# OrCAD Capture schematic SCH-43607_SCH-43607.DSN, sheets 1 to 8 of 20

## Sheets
1 P01_TITLE: title: FRWYLS1046A-PA; rev: B; company: NXP Semiconductors; note: SCH-43607 PDF: SPF-43607; note: 6501 William Cannon Drive West; note: Austin, TX 78735-8598
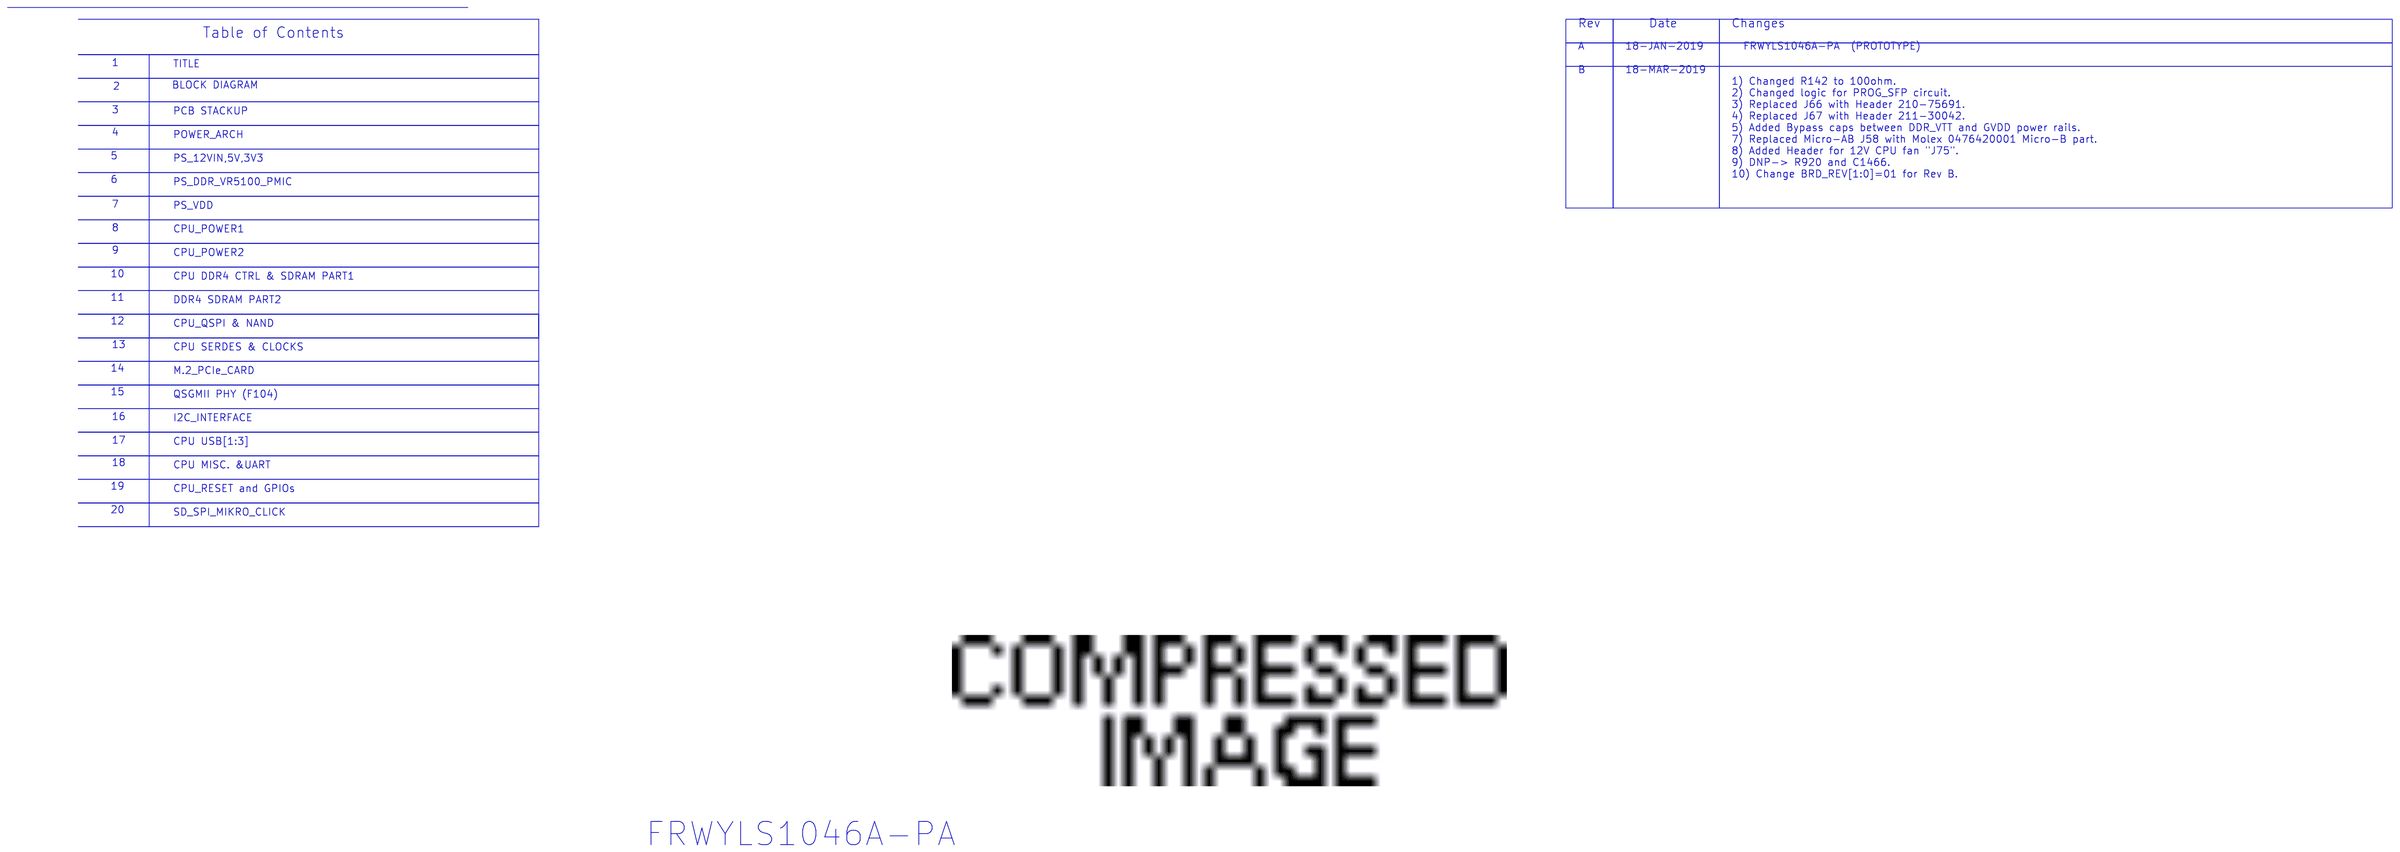
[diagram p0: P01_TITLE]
2 P02_BLOCK DIAGRAM
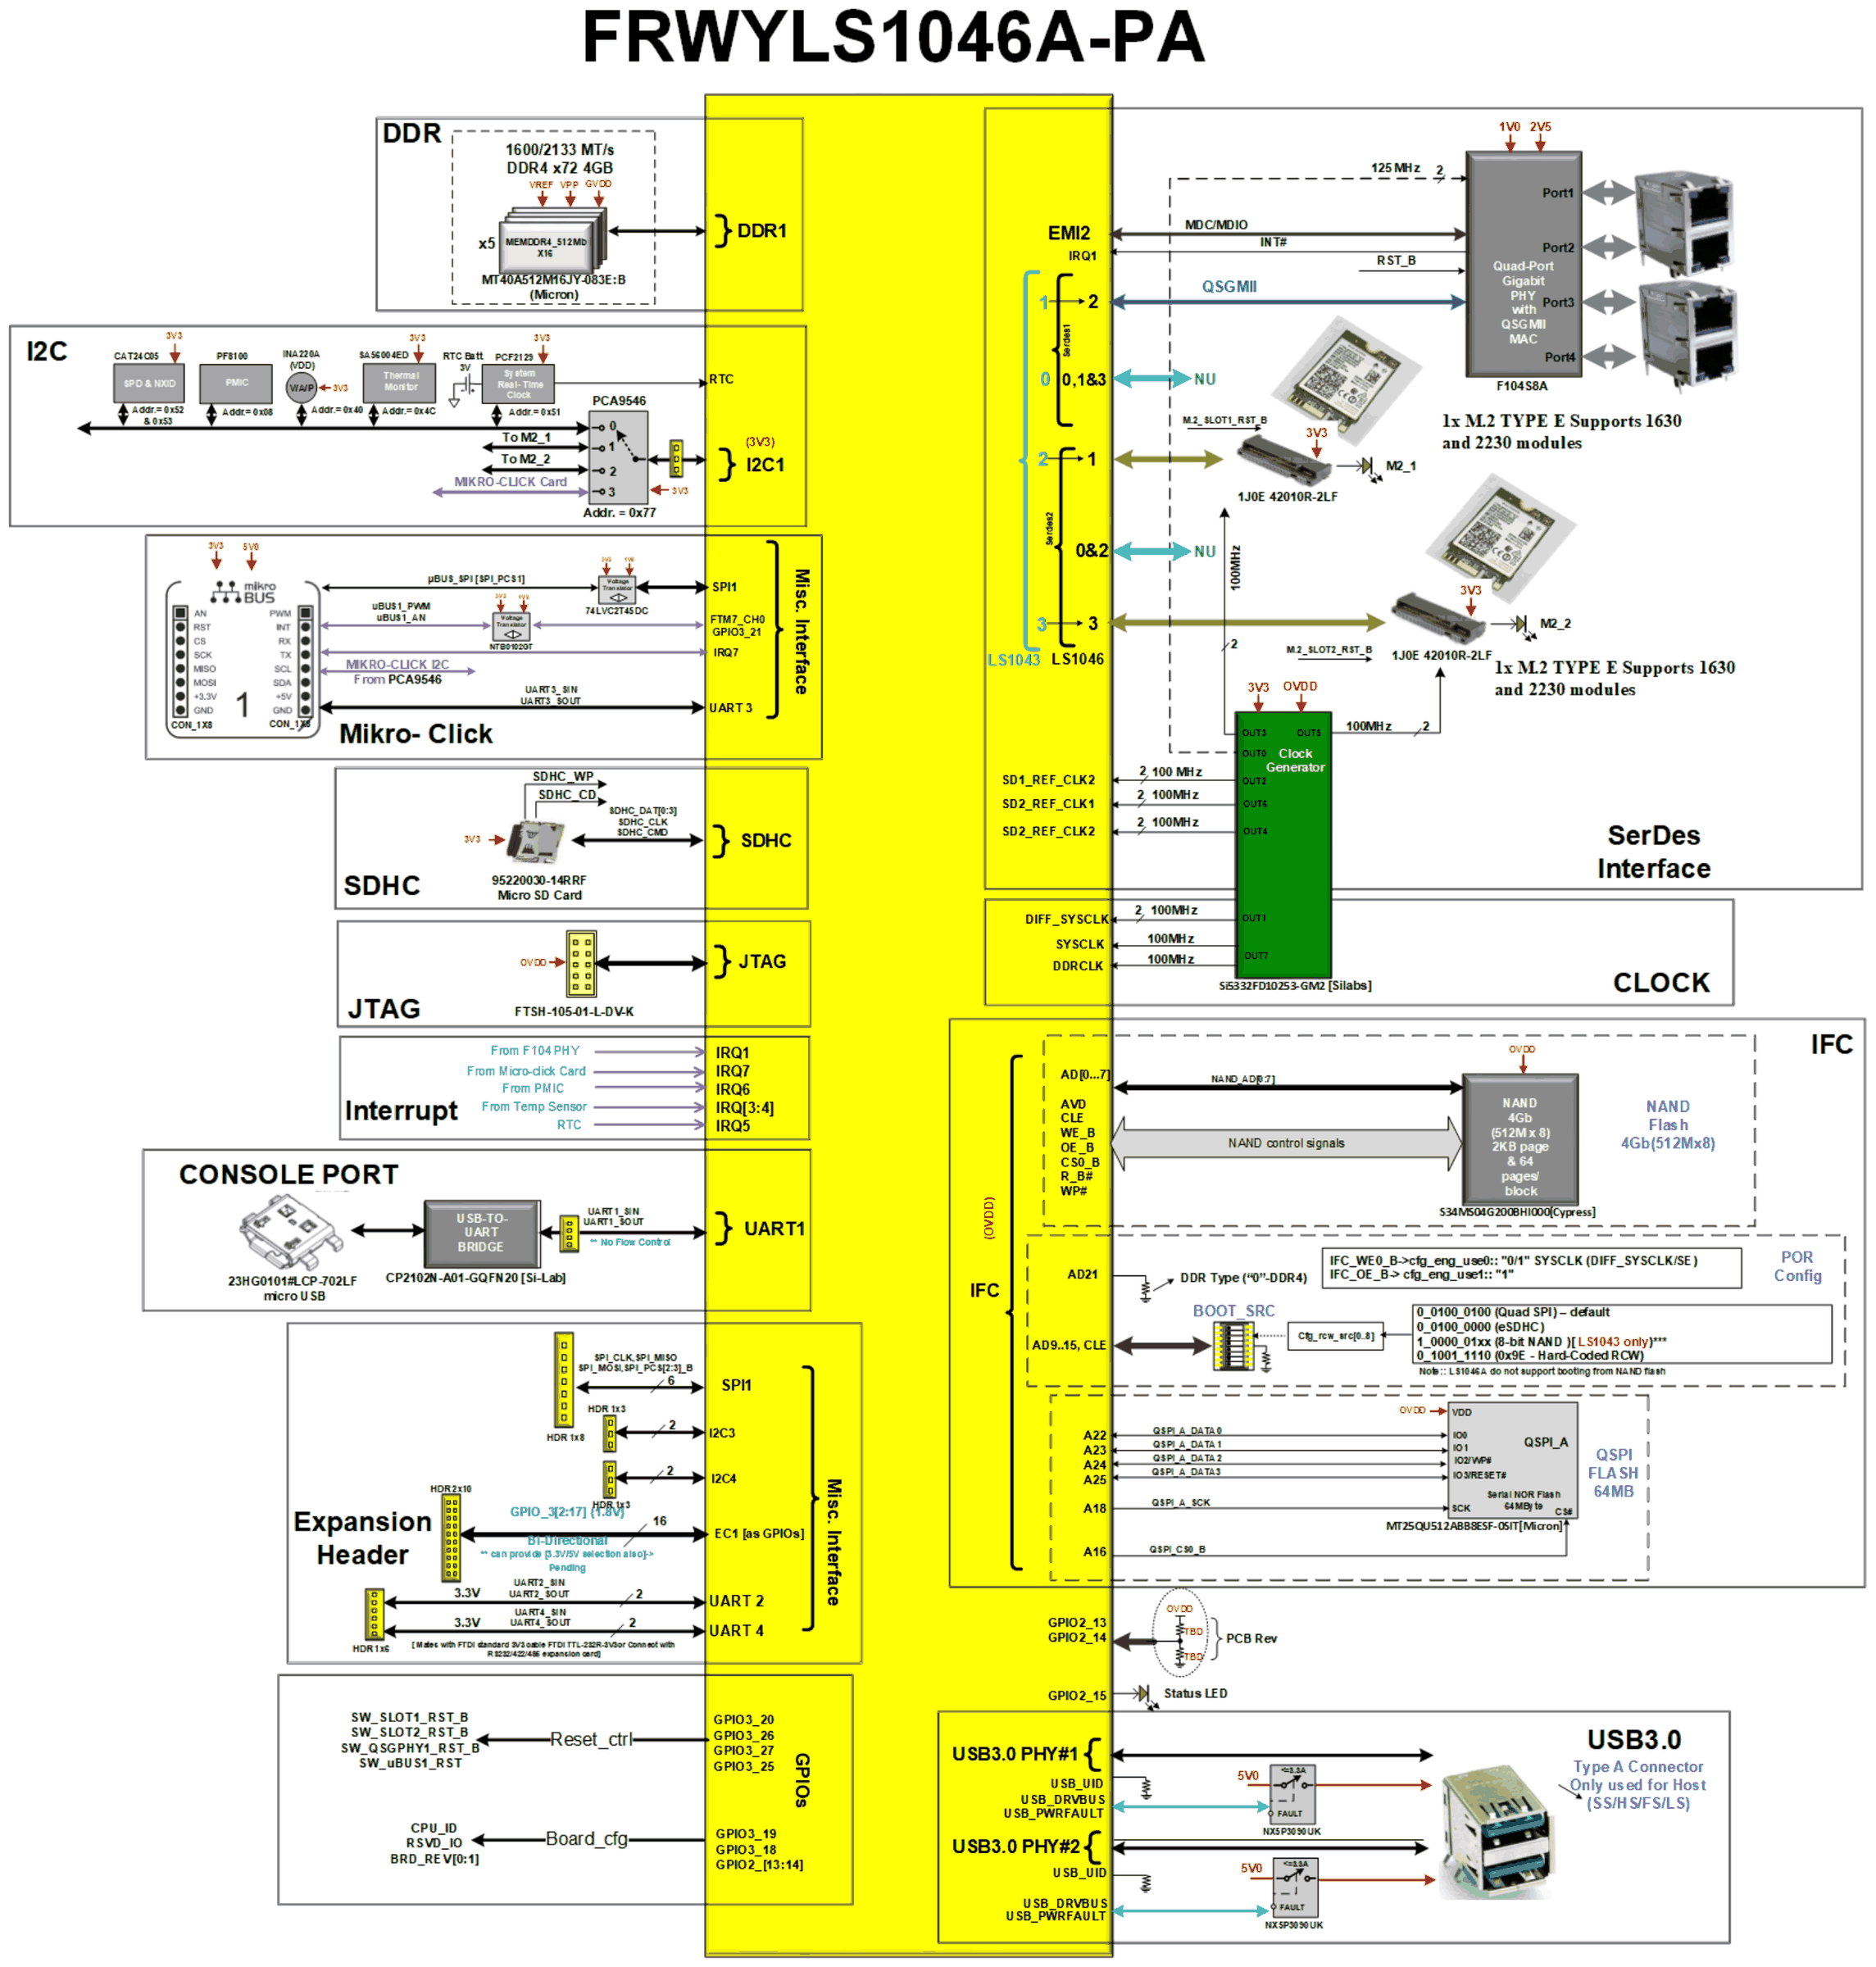
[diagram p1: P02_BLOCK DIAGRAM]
3 P03_PCB STACKUP
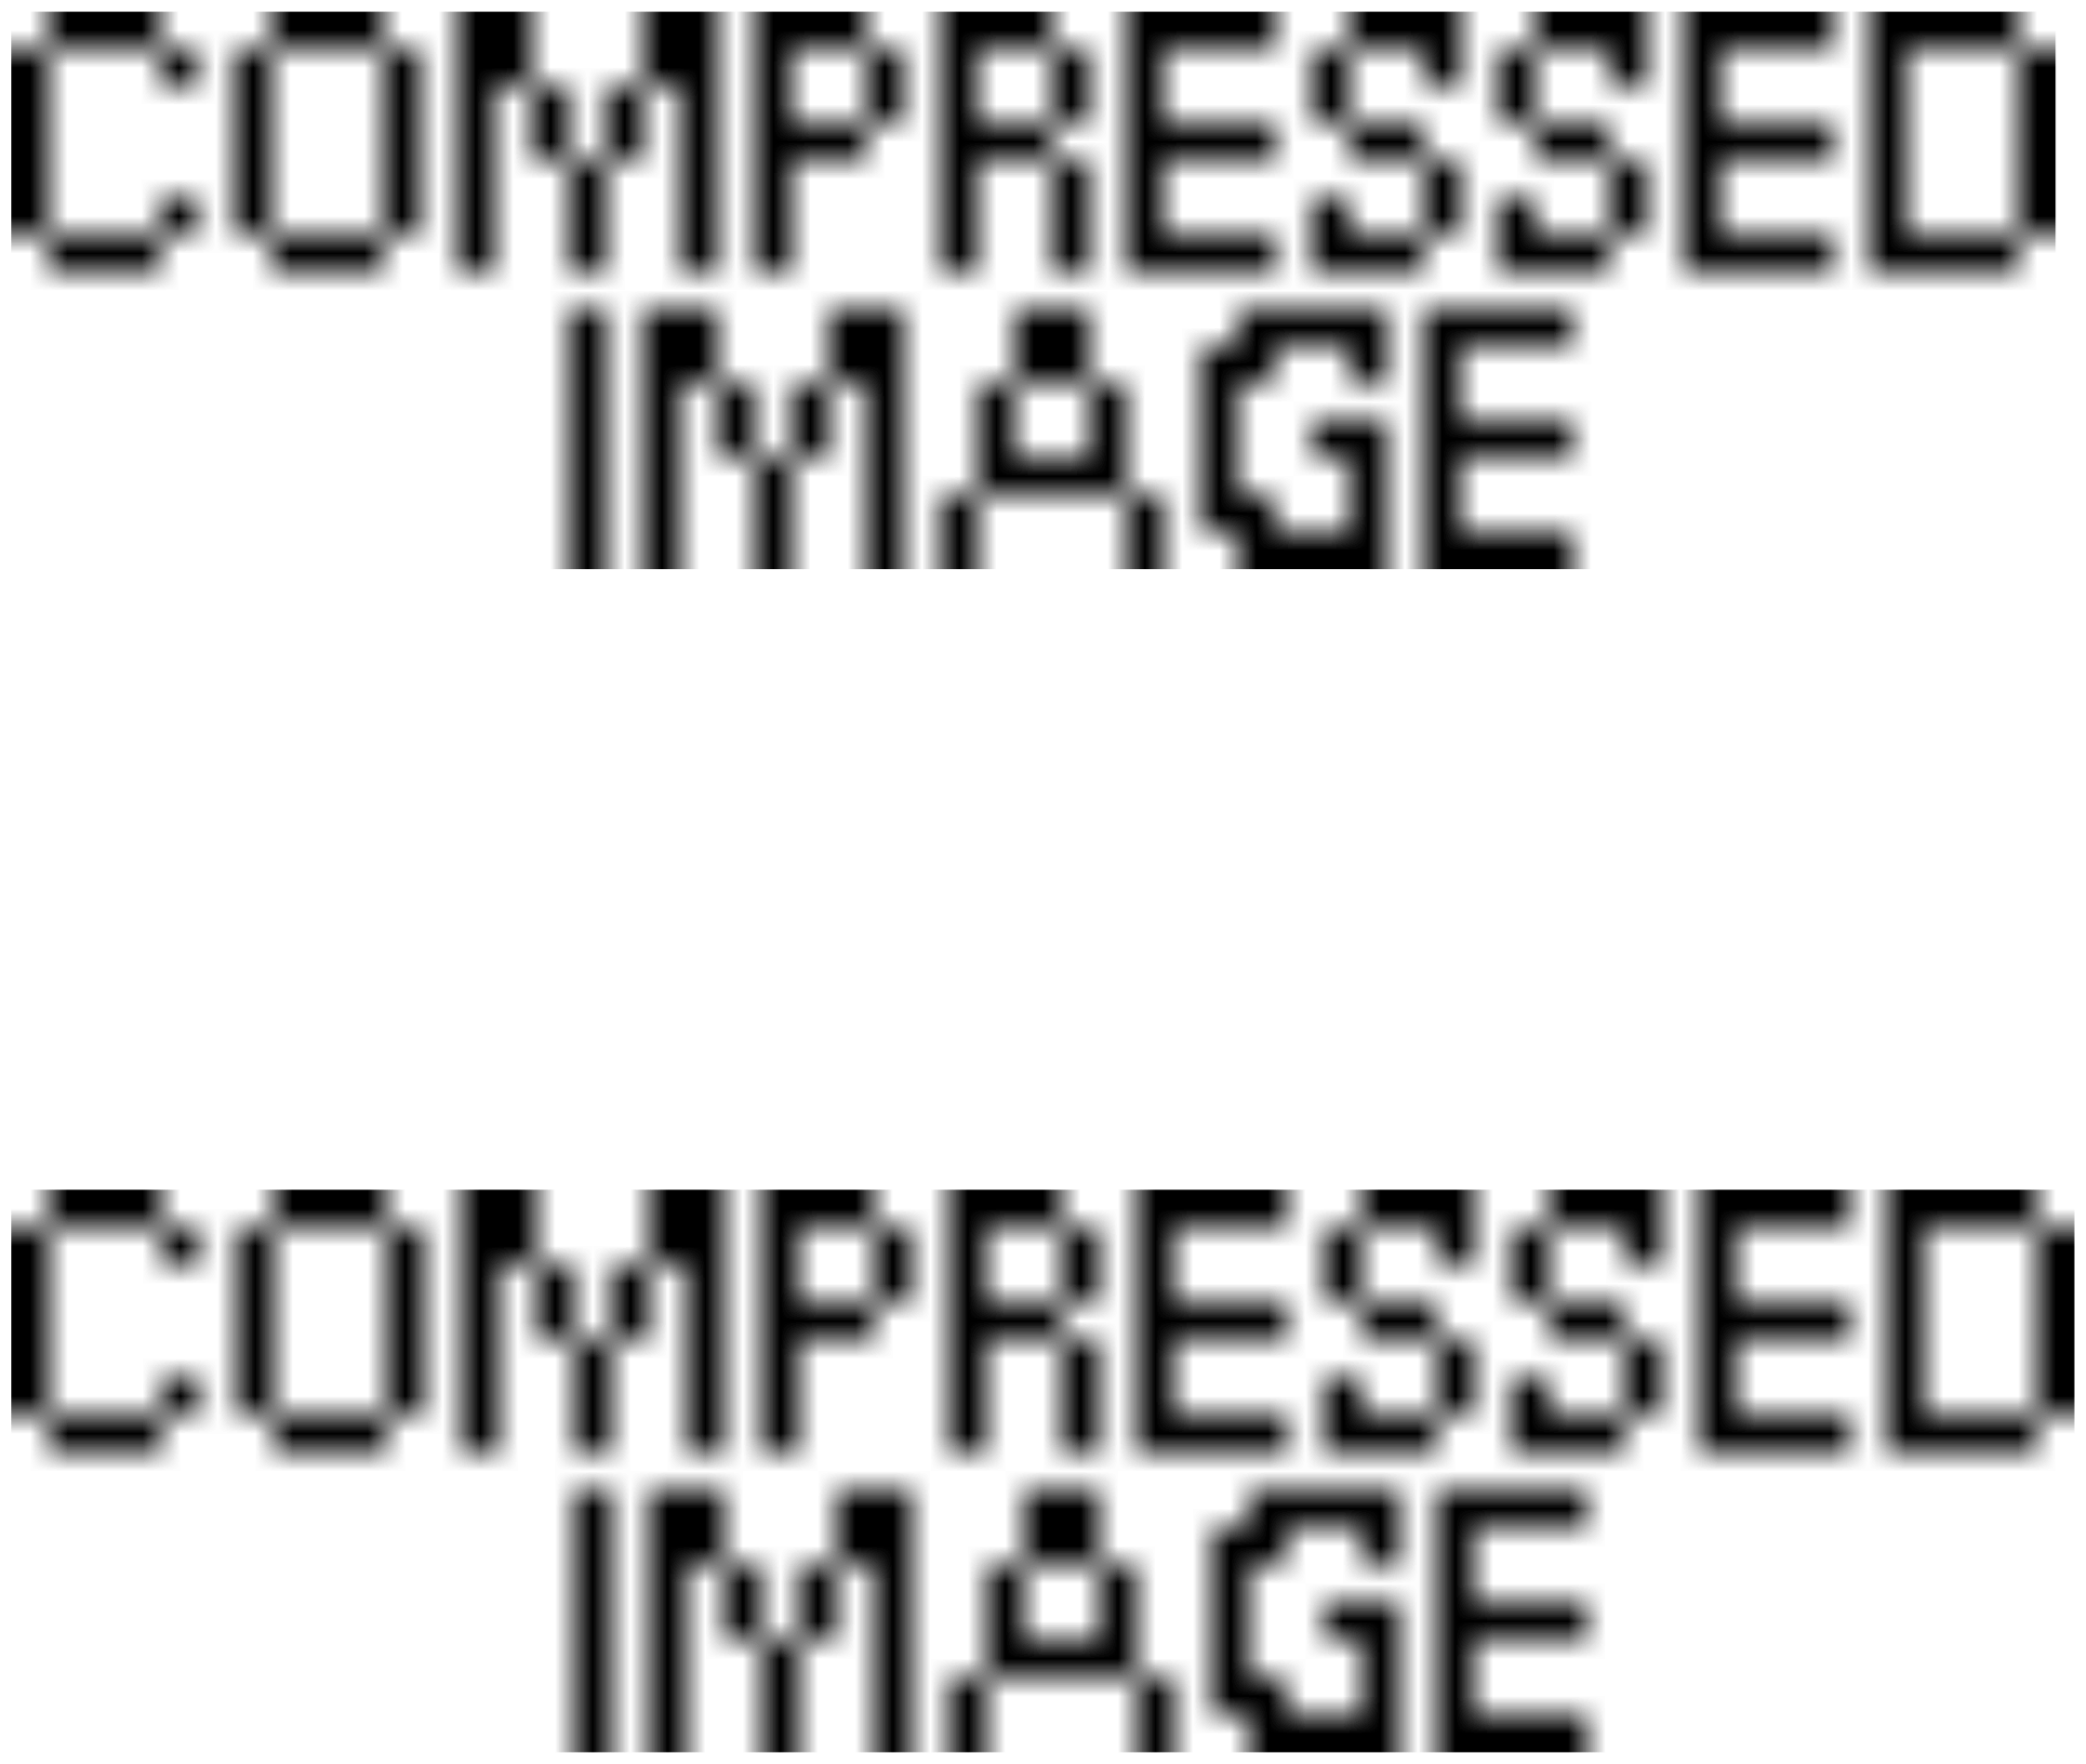
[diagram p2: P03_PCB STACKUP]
4 P04_POWER_ARCH
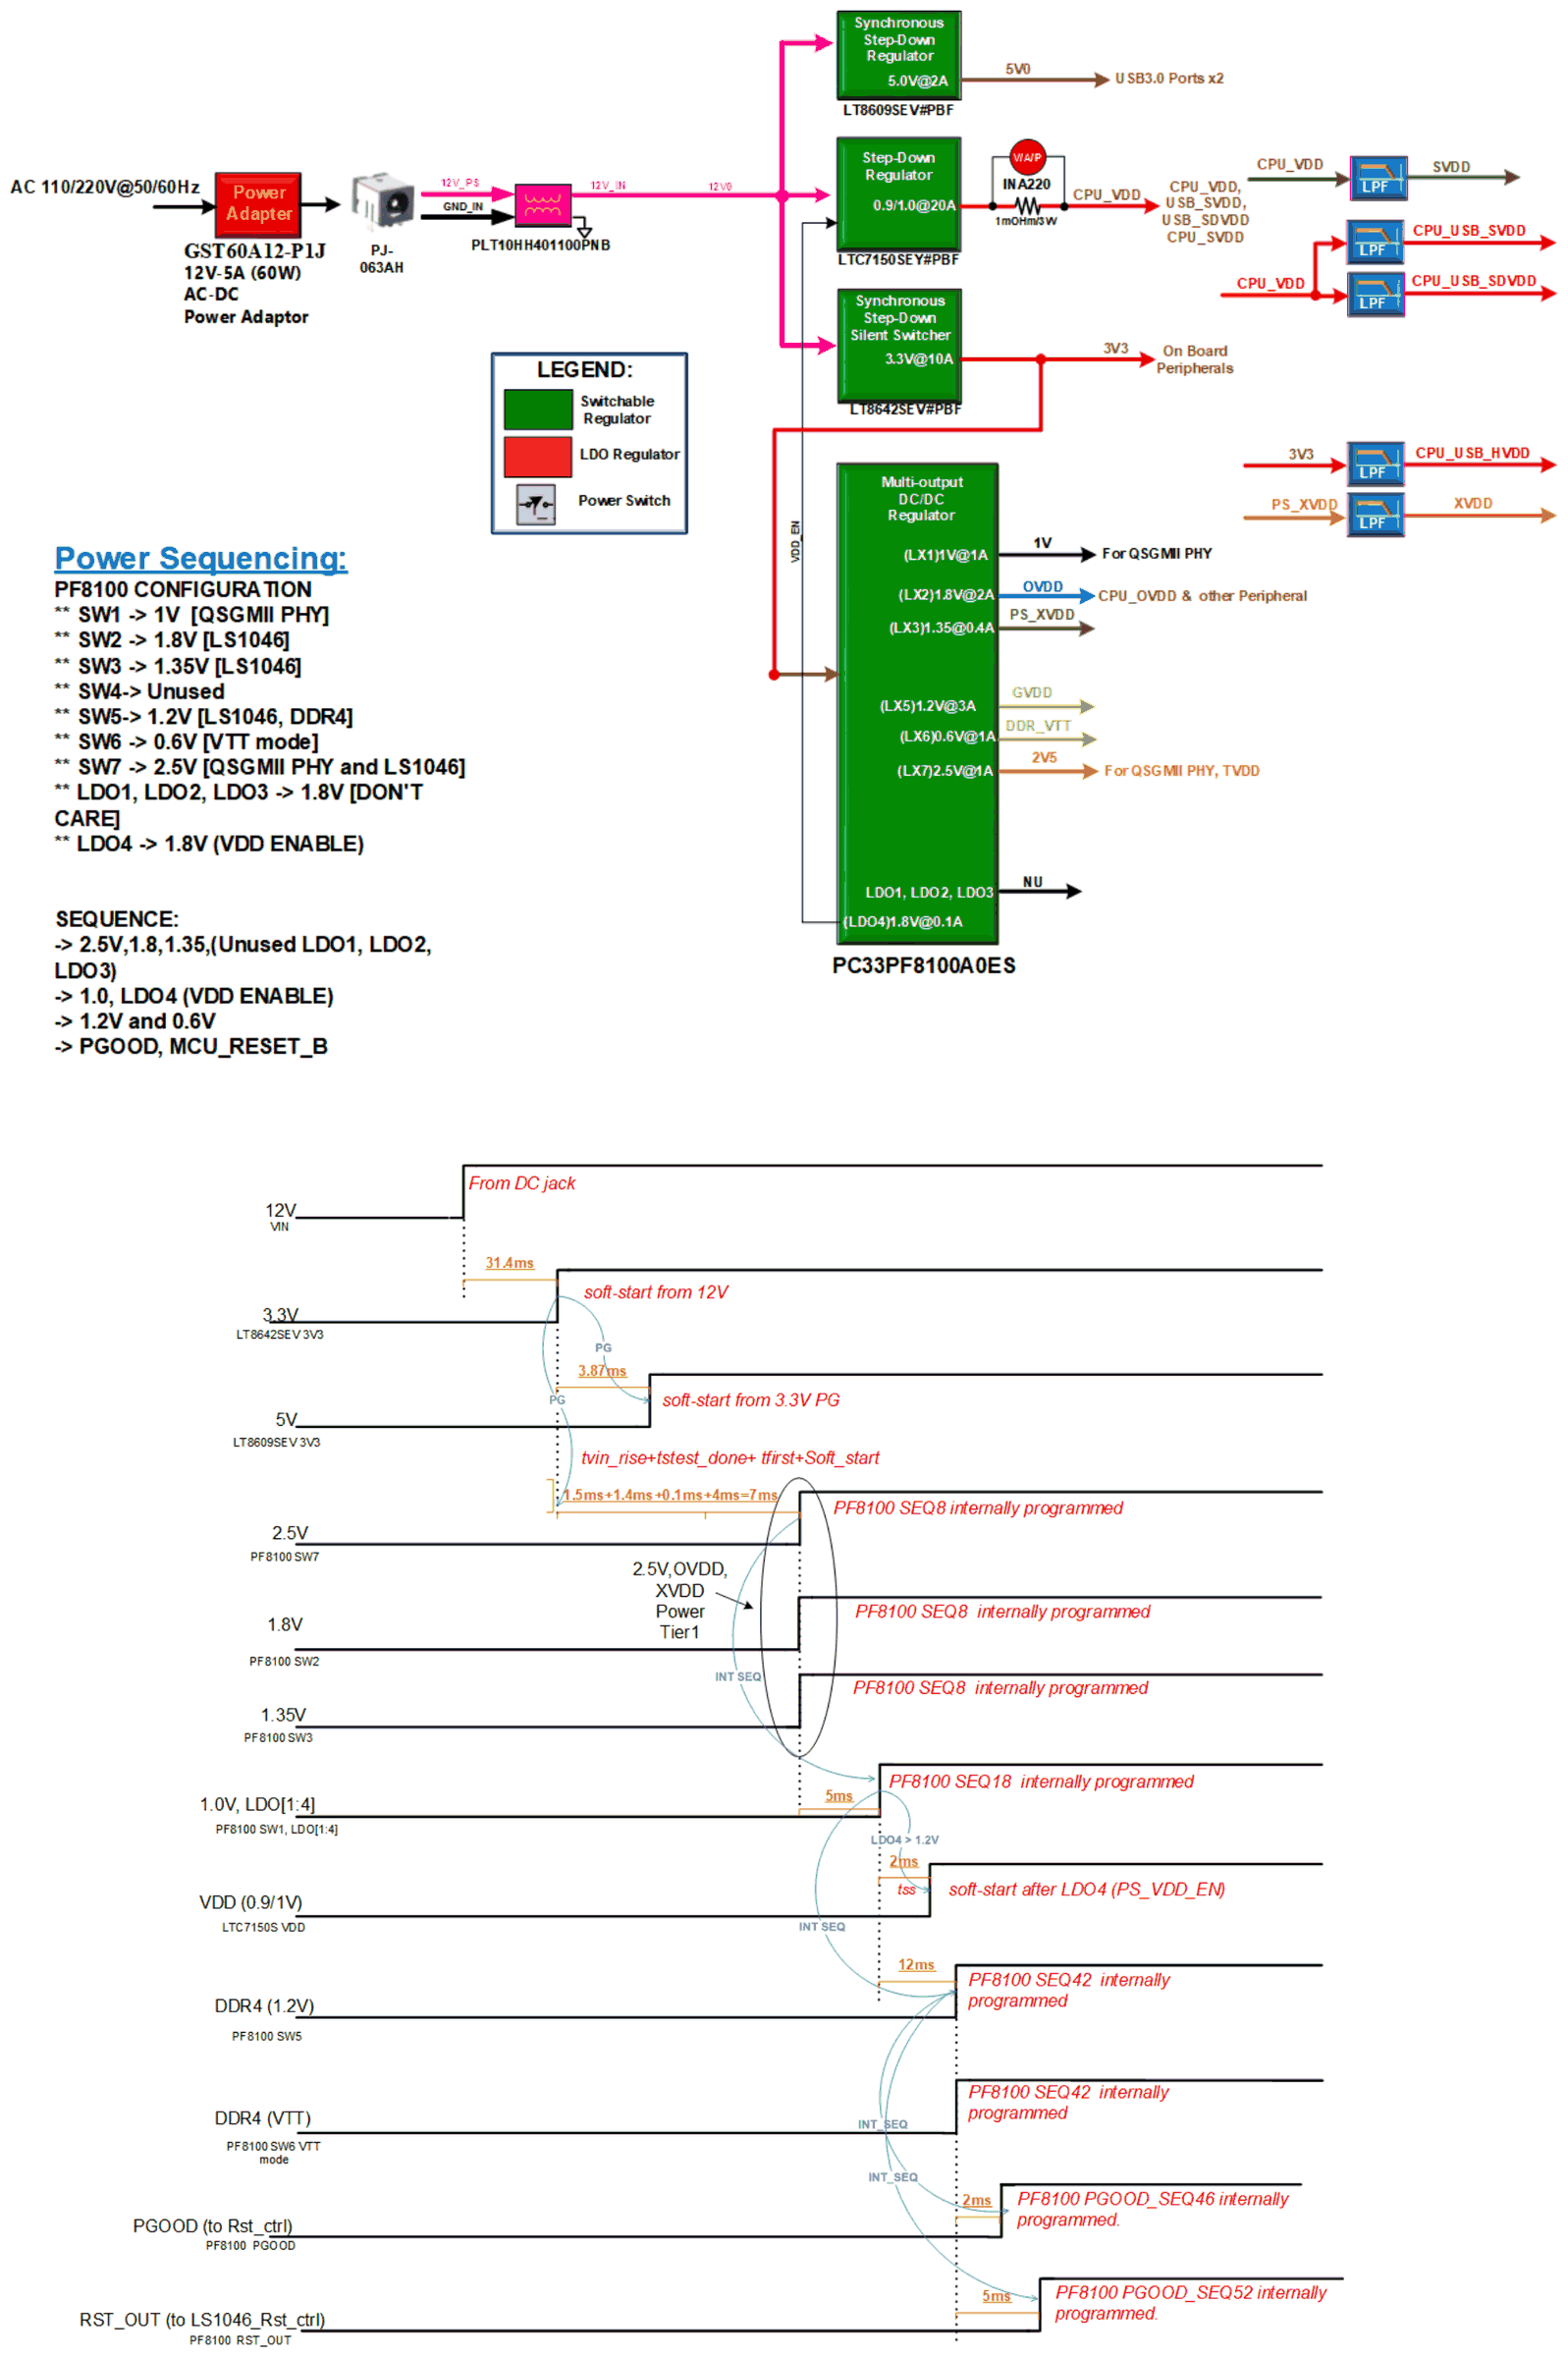
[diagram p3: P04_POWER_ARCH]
5 P05_PS_12VIN,5V,3V3: size C
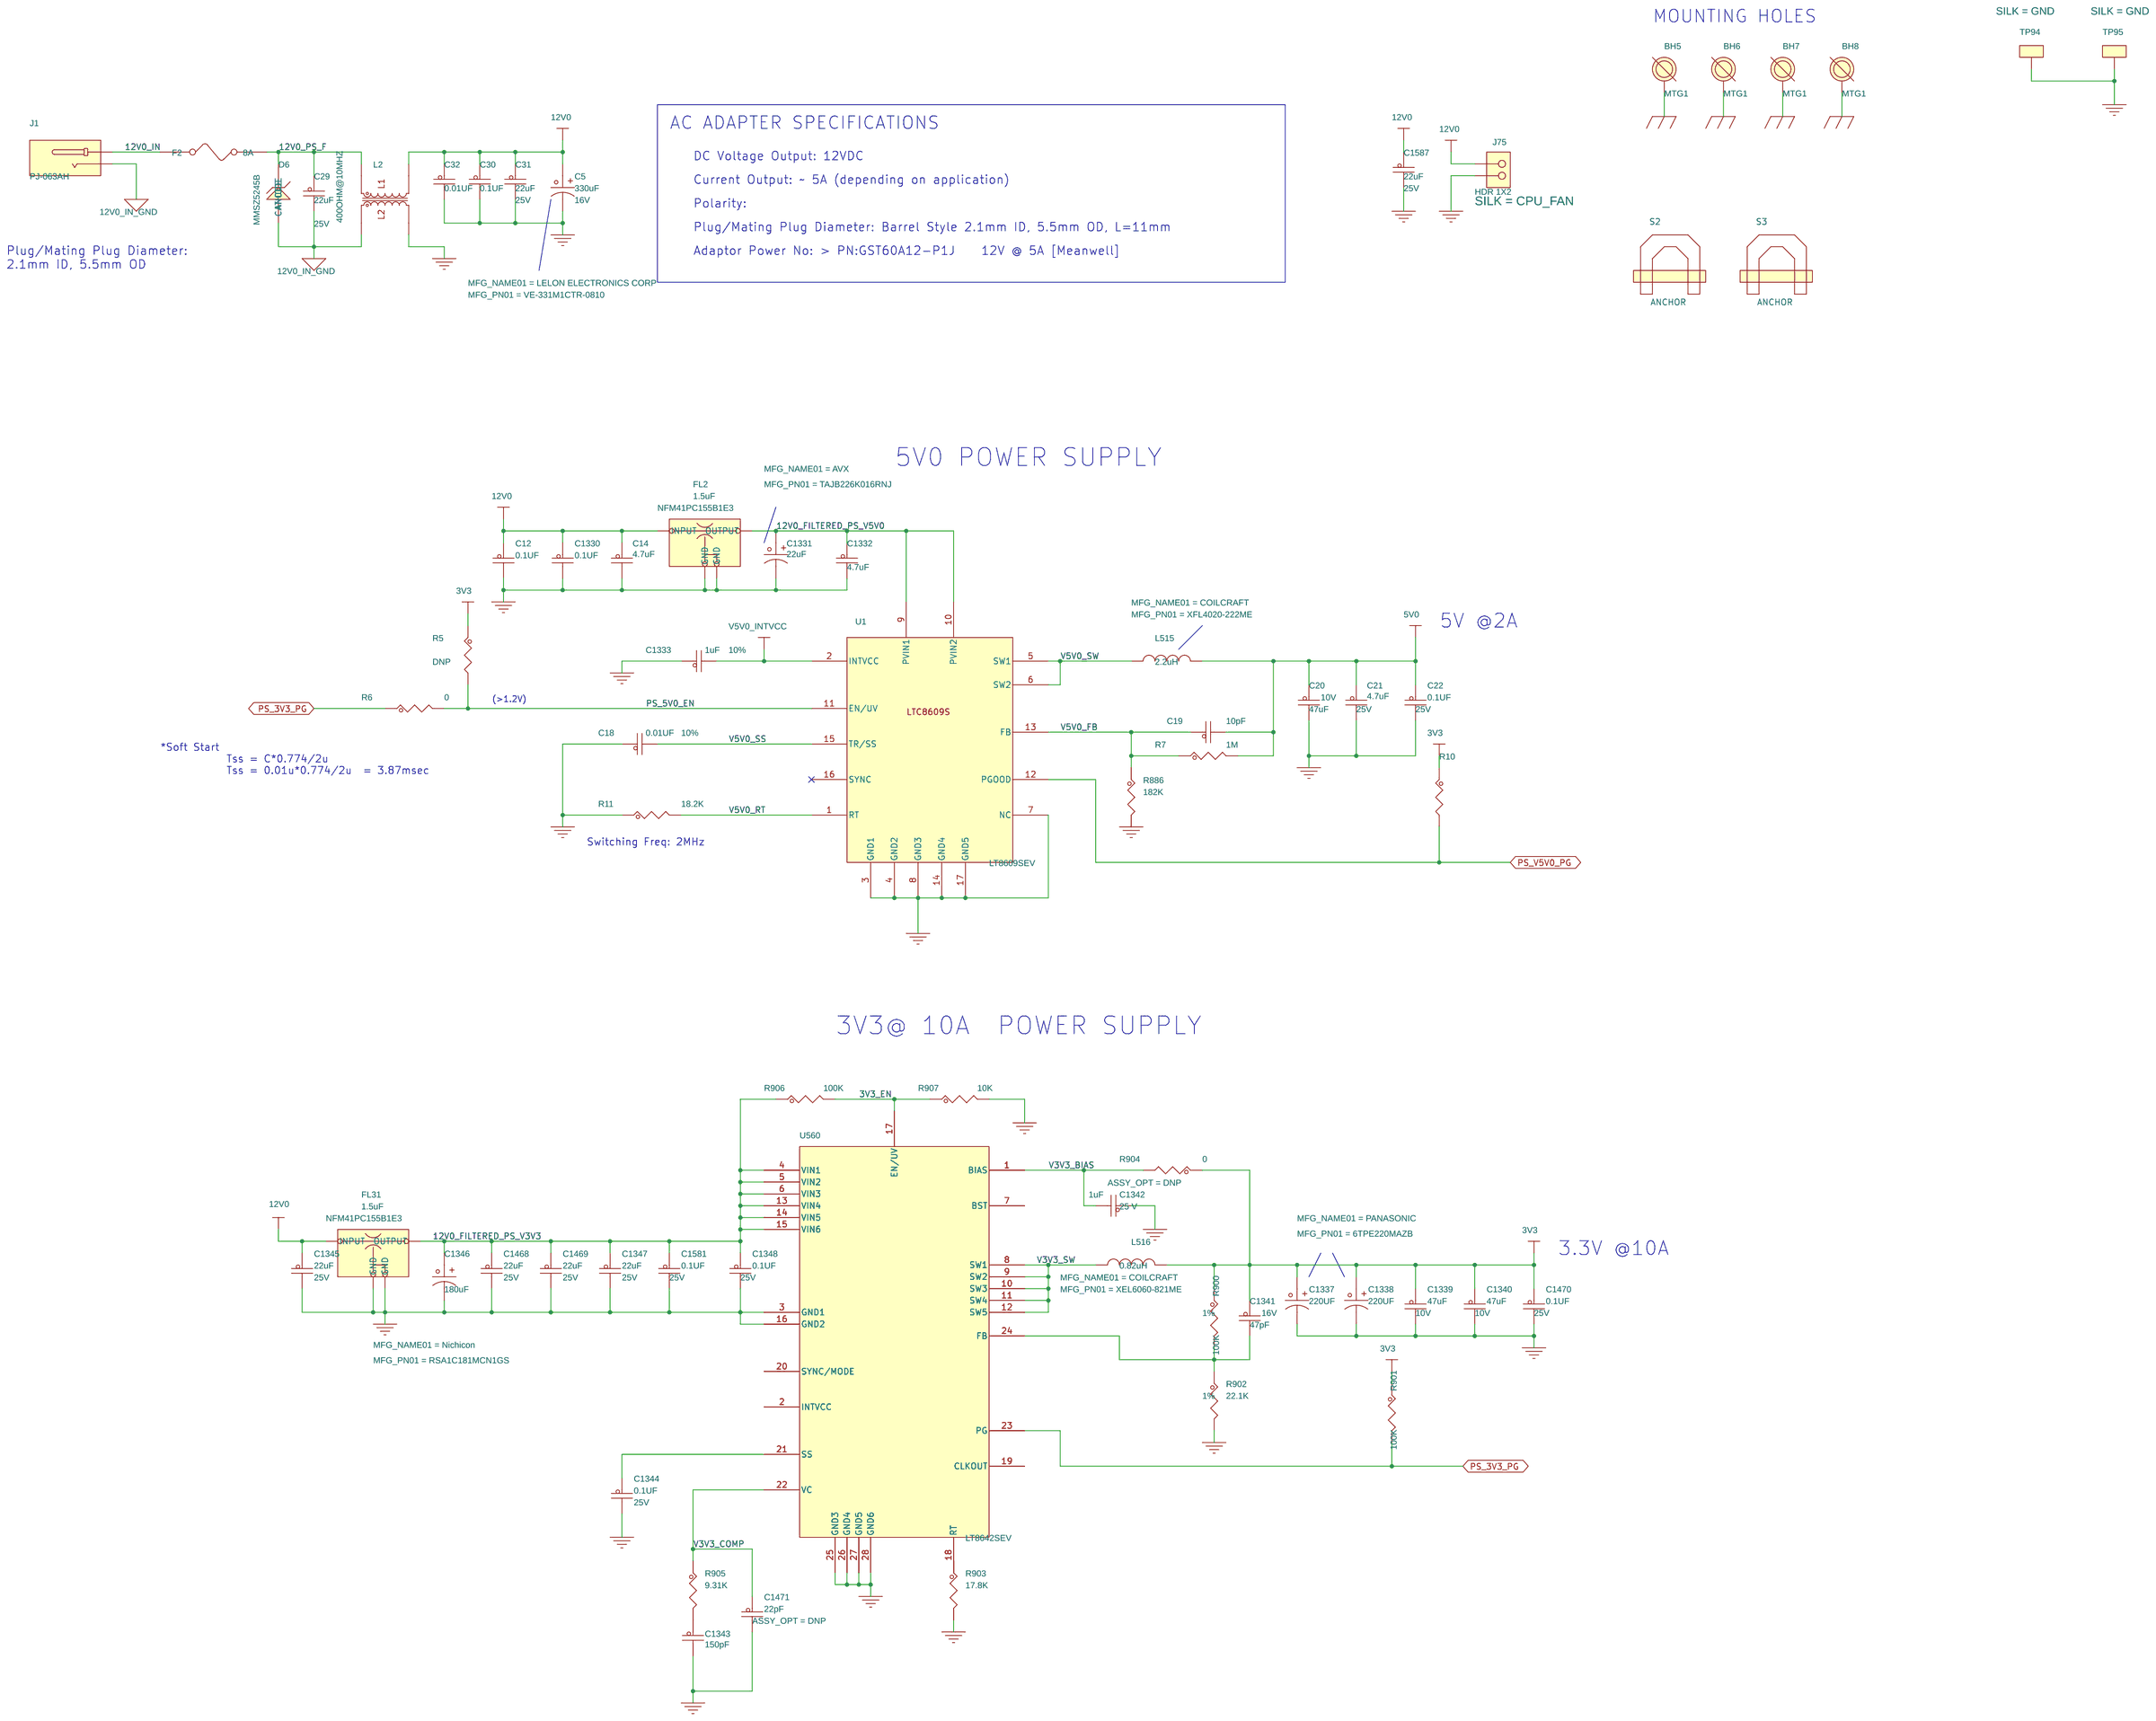
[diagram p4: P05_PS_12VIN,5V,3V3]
6 P06_PS_DDR_PF8100_PMIC: size C
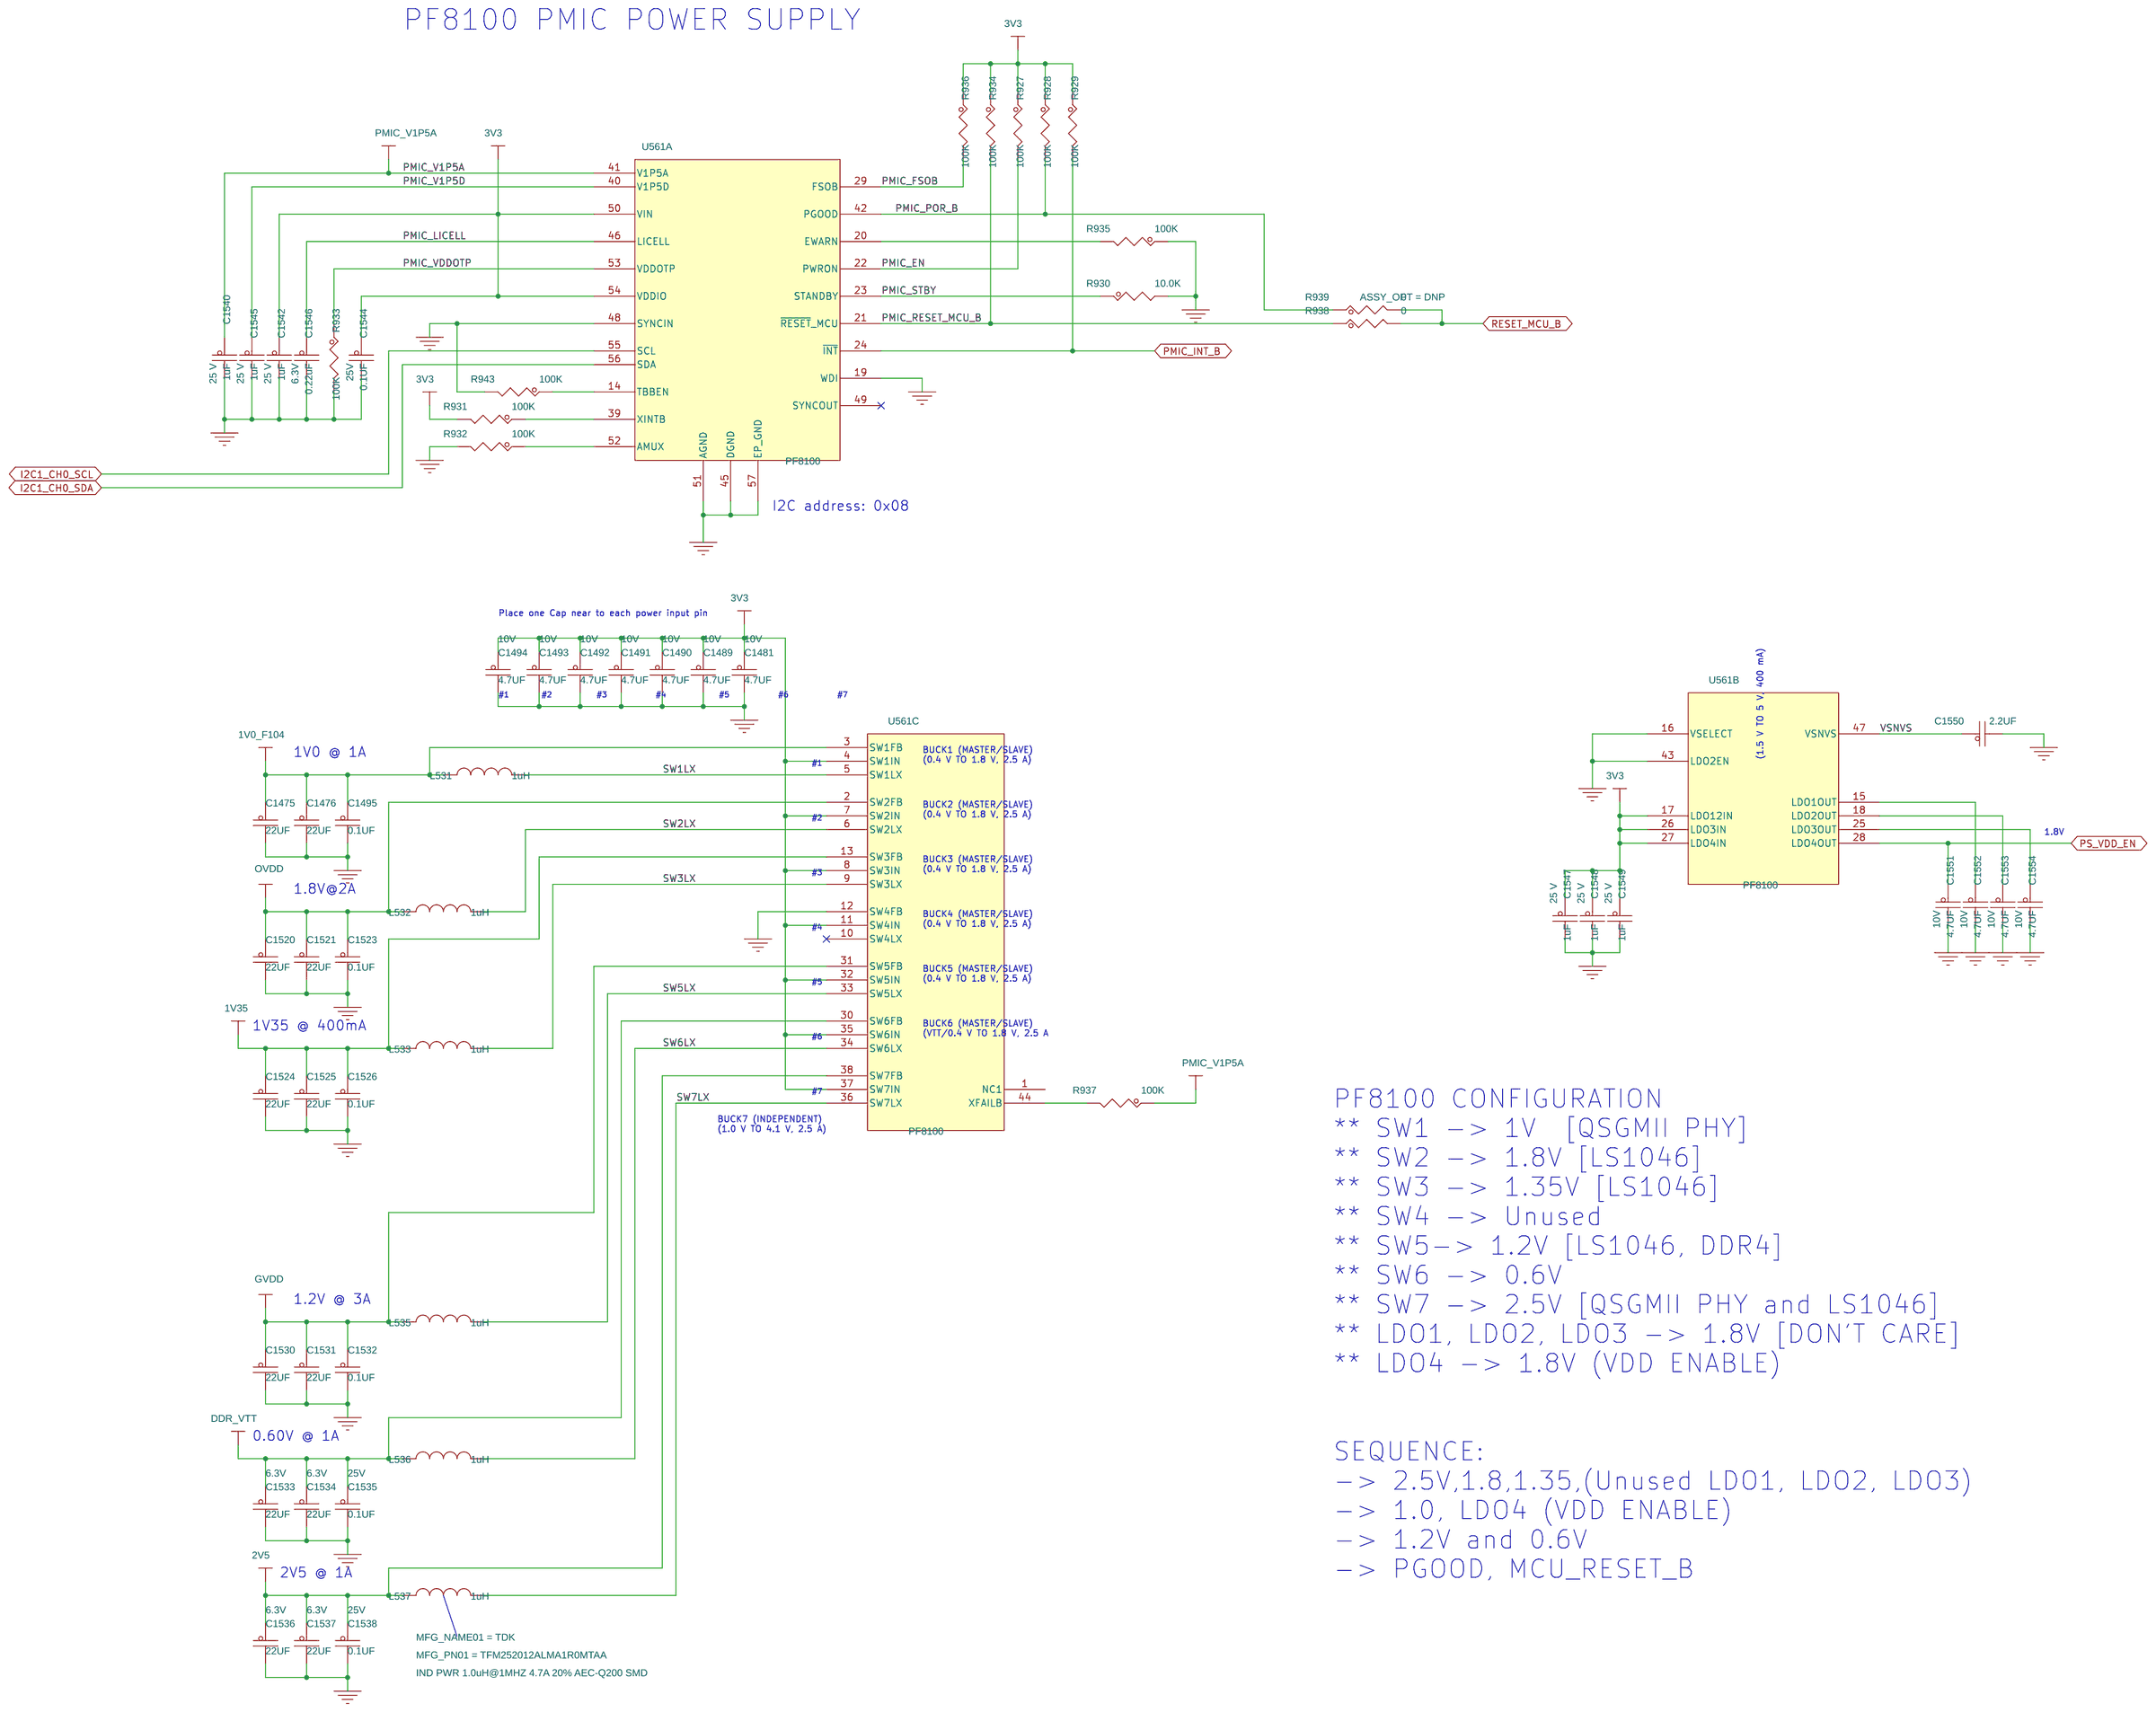
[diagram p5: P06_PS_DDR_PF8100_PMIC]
7 P07_PS_VDD: size C
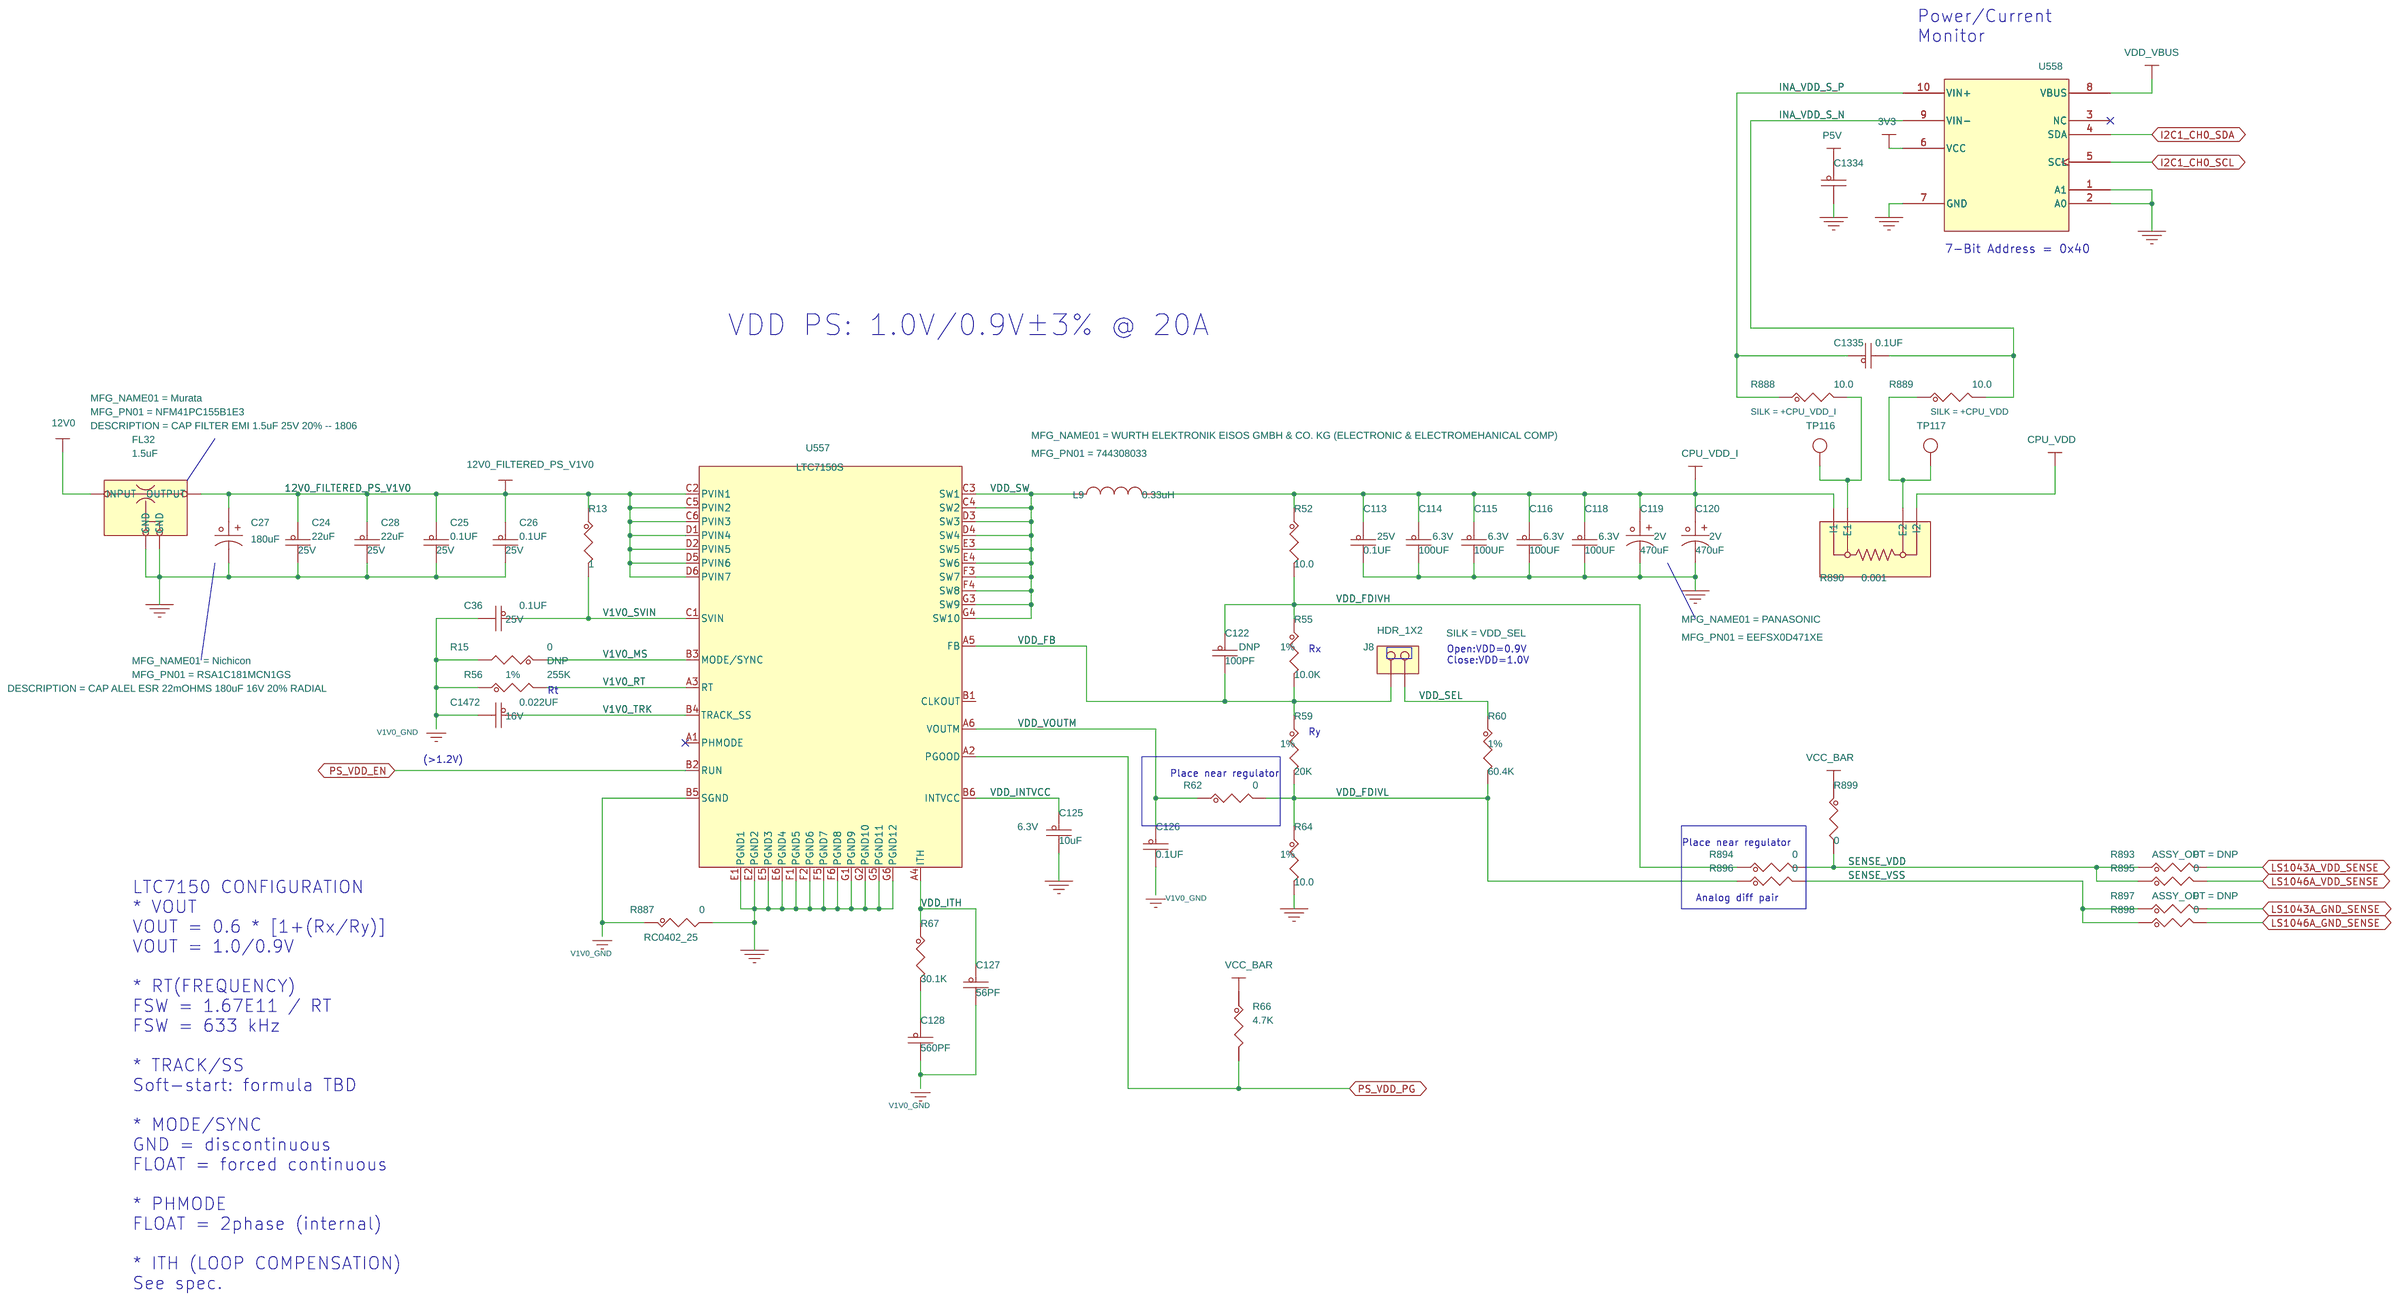
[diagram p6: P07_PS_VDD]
8 P08_CPU POWER1: size C
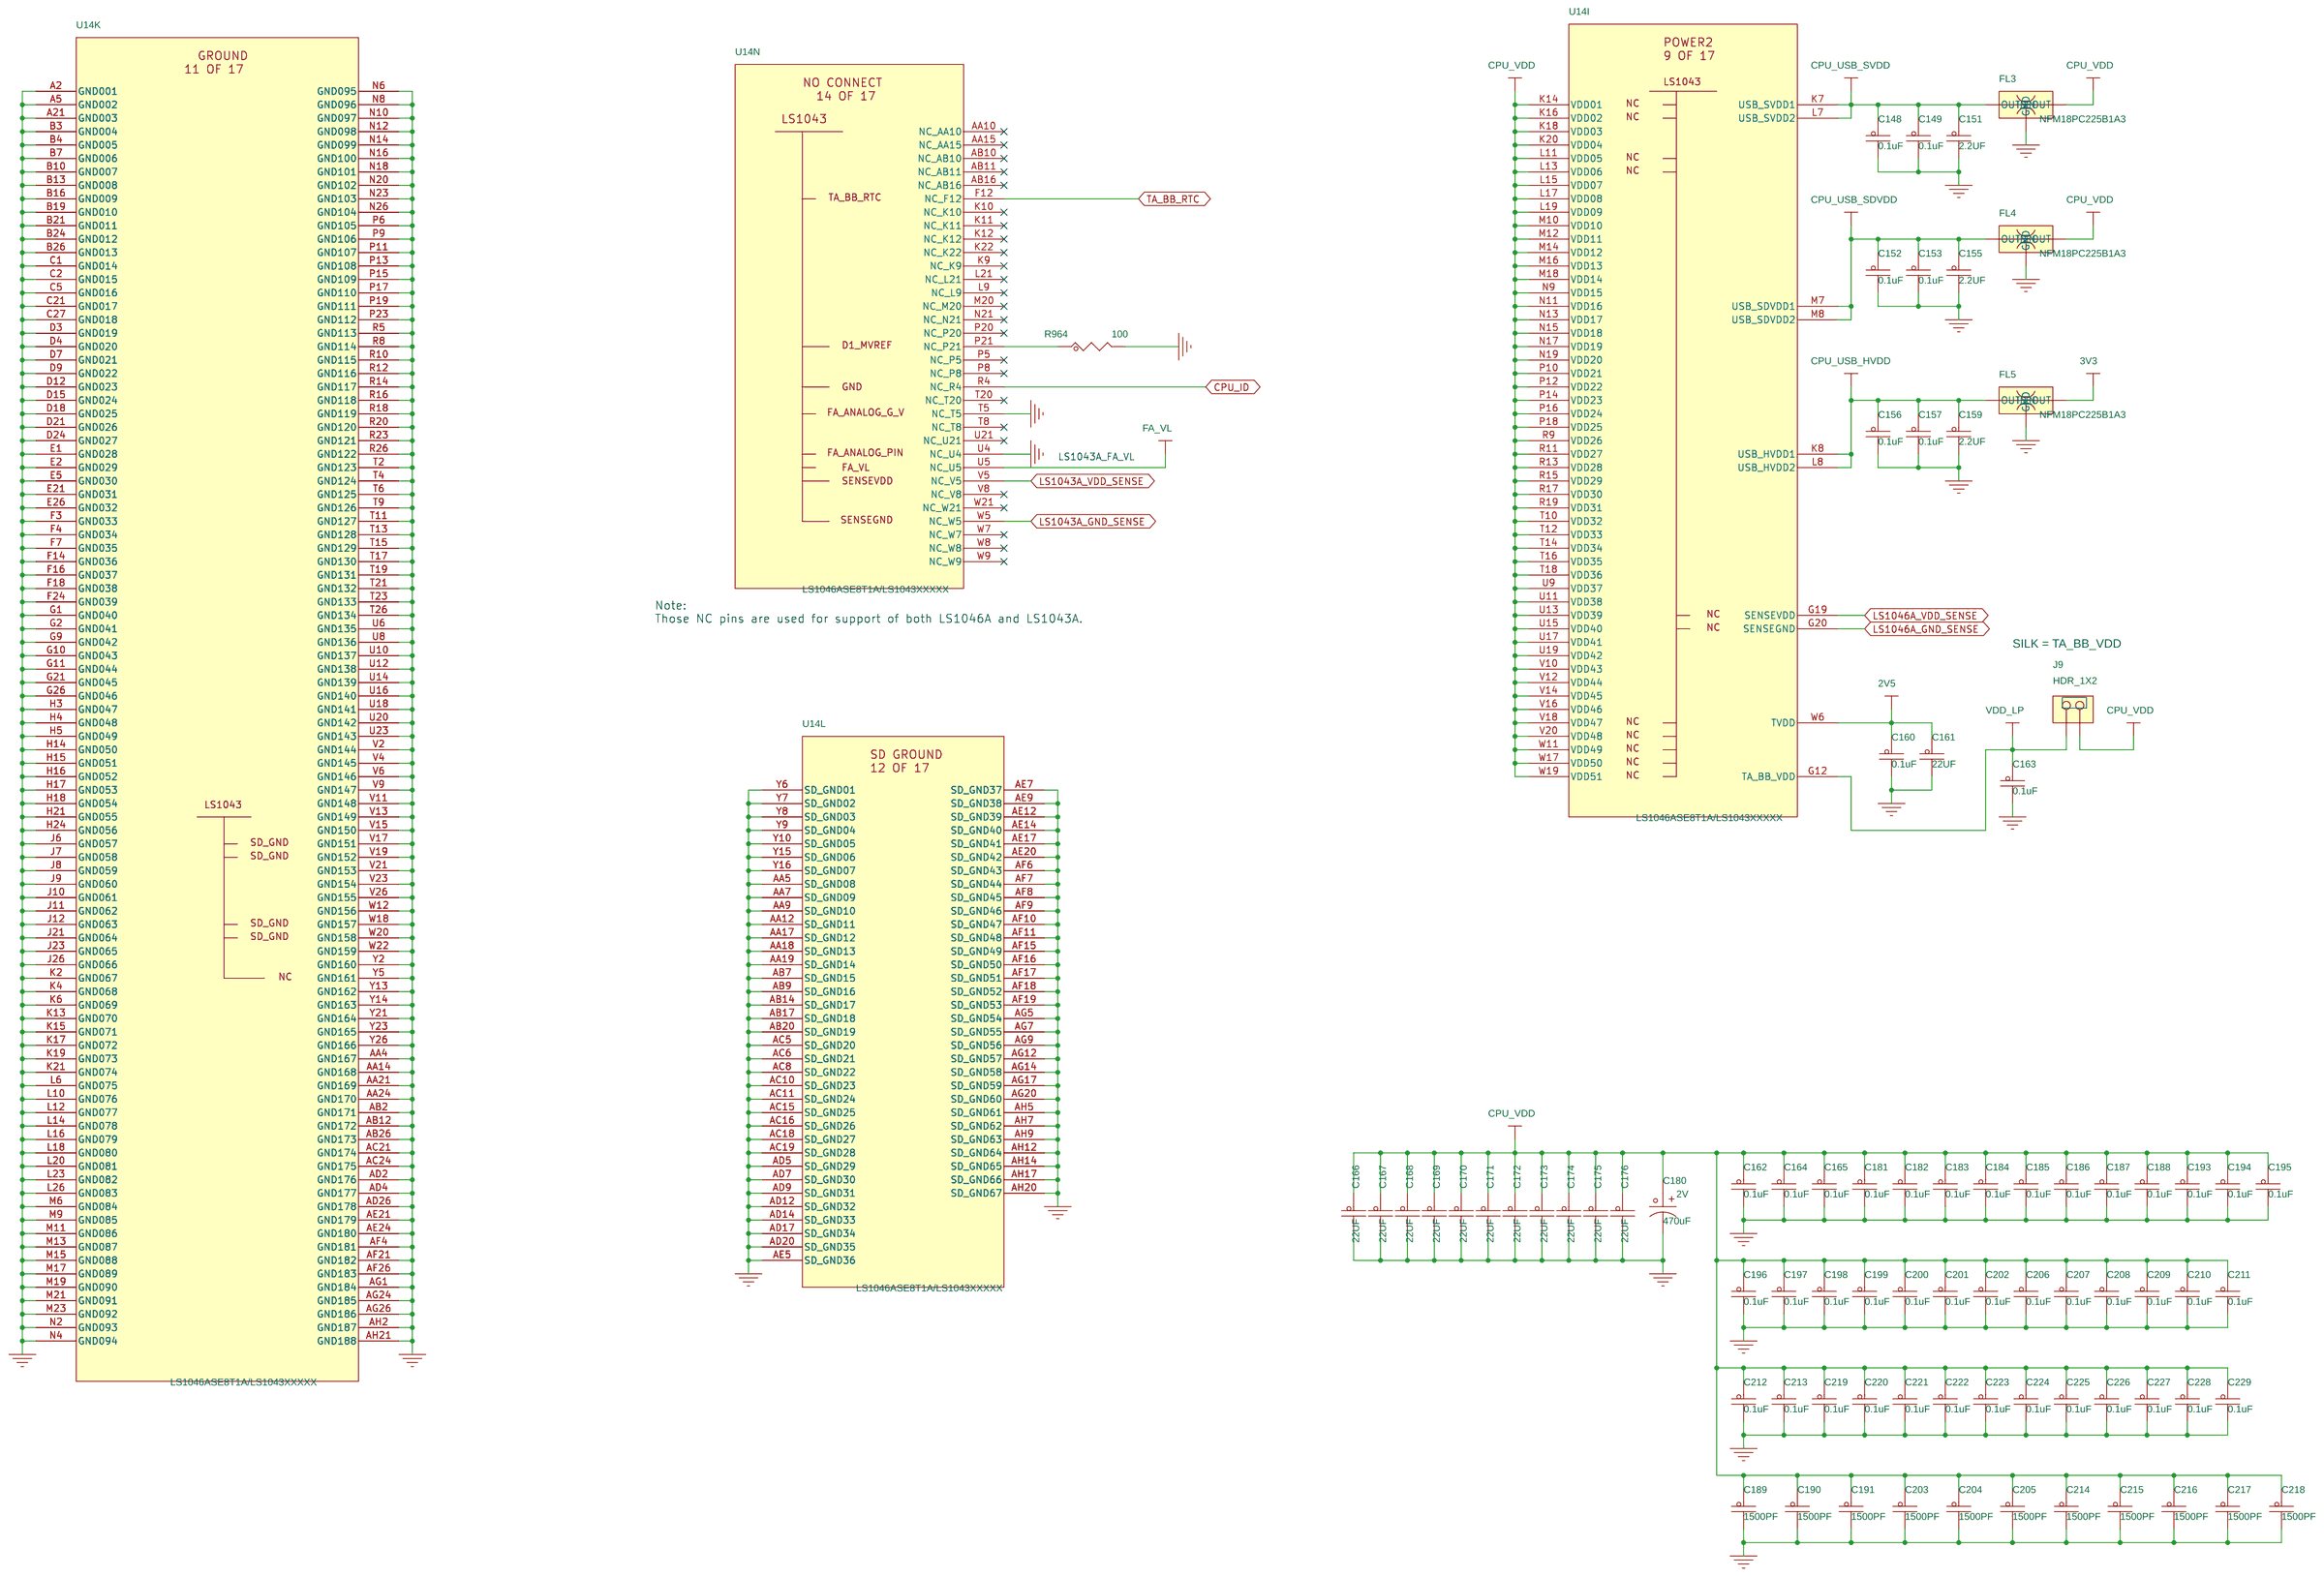
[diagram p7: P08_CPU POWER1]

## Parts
sheet P05_PS_12VIN,5V,3V3
BH5  MTG1  [pmc_mech_hole]
BH6  MTG1  [pmc_mech_hole]
BH7  MTG1  [pmc_mech_hole]
BH8  MTG1  [pmc_mech_hole]
C5  330uF  [8X10P8]
C12  0.1UF  [CC0402_25]
C14  4.7uF  [CC0805_OV]
C18  0.01UF  [CC0402_25]
C19  10pF  [CC0402_25]
C20  47uF  [CC0805_OV]
C21  4.7uF  [CC0805_OV]
C22  0.1UF  [CC0402_25]
C29  22uF  [CC0805_OV]
C30  0.1UF  [CC0402_25]
C31  22uF  [CC0805_OV]
C32  0.01UF  [CC0402_25]
C1330  0.1UF  [CC0402_25]
C1331  22uF  [cc3528-21]
C1332  4.7uF  [CC0805_OV]
C1333  1uF  [CC0402_25]
C1337  220UF  [cc3528-21]
C1338  220UF  [cc3528-21]
C1339  47uF  [CC0805_OV]
C1340  47uF  [CC0805_OV]
C1341  47pF  [CC0402_25]
C1342  1uF  [CC0402_25]
C1343  150pF  [CC0402_25]
C1344  0.1UF  [CC0402_25]
C1345  22uF  [CC0805_OV]
C1346  180uF  [cce6p8x6p8]
C1347  22uF  [CC0805_OV]
C1348  0.1UF  [CC0402_25]
C1468  22uF  [CC0805_OV]
C1469  22uF  [CC0805_OV]
C1470  0.1UF  [CC0402_25]
C1471  22pF  [CC0402_25]
C1581  0.1UF  [CC0402_25]
C1587  22uF  [CC0805_OV]
D6  MMSZ5245B  [sod123]
F2  8A  [fuse_3p4x1p8]
FL2  1.5uF  [CC_NFM41P_1806]
FL31  1.5uF  [CC_NFM41P_1806]
J1  PJ-063AH  [con_dcjack_063bh_th_ra]
J75  HDR 1X2  [HDR102]
L2  400OHM@10MHZ  [ind4_7x13_sm]
L515  2.2uH  [ind2_4p3sq_xfl4020]
L516  0.82uH  [ind2_xal60xx_102]
R5  1.0K  [RC0402_25]
R6  0  [RC0402_25]
R7  1M  [RC0402_25]
R10  1.0K  [RC0402_25]
R11  18.2K  [RC0402_25]
R886  182K  [RC0402_25]
R900  100K  [RC0402_25]
R901  100K  [RC0402_25]
R902  22.1K  [RC0402_25]
R903  17.8K  [RC0402_25]
R904  0  [RC0402_25]
R905  9.31K  [RC0402_25]
R906  100K  [RC0402_25]
R907  10K  [RC0402_25]
S2  ANCHOR  [ANCHOR]
S3  ANCHOR  [ANCHOR]
TP94  5006  [tp_th_063]
TP95  5006  [tp_th_063]
U1  LT8609SEV  [qfn16_0p5_3x3_ep_4mp]
U560  LT8642SEV  [qfn24_4X4mm_4ep]
sheet P06_PS_DDR_PF8100_PMIC
C1475  22UF  [CC0603_OV]
C1476  22UF  [CC0603_OV]
C1481  4.7UF  [CC0402_25]
C1489  4.7UF  [CC0402_25]
C1490  4.7UF  [CC0402_25]
C1491  4.7UF  [CC0402_25]
C1492  4.7UF  [CC0402_25]
C1493  4.7UF  [CC0402_25]
C1494  4.7UF  [CC0402_25]
C1495  0.1UF  [CC0402_25]
C1520  22UF  [CC0603_OV]
C1521  22UF  [CC0603_OV]
C1523  0.1UF  [CC0402_25]
C1524  22UF  [CC0603_OV]
C1525  22UF  [CC0603_OV]
C1526  0.1UF  [CC0402_25]
C1530  22UF  [CC0603_OV]
C1531  22UF  [CC0603_OV]
C1532  0.1UF  [CC0402_25]
C1533  22UF  [CC0603_OV]
C1534  22UF  [CC0603_OV]
C1535  0.1UF  [CC0402_25]
C1536  22UF  [CC0603_OV]
C1537  22UF  [CC0603_OV]
C1538  0.1UF  [CC0402_25]
C1540  1uF  [CC0402_25]
C1542  1uF  [CC0402_25]
C1544  0.1UF  [CC0402_25]
C1545  1uF  [CC0402_25]
C1546  0.22uF  [CC0201]
C1547  1uF  [CC0402_25]
C1548  1uF  [CC0402_25]
C1549  1uF  [CC0402_25]
C1550  2.2UF  [CC0402_25]
C1551  4.7UF  [CC0402_25]
C1552  4.7UF  [CC0402_25]
C1553  4.7UF  [CC0402_25]
C1554  4.7UF  [CC0402_25]
L531  1uH  [ind2520]
L532  1uH  [ind2520]
L533  1uH  [ind2520]
L535  1uH  [ind2520]
L536  1uH  [ind2520]
L537  1uH  [ind2520]
R927  100K  [RC0402_25]
R928  100K  [RC0402_25]
R929  100K  [RC0402_25]
R930  10.0K  [RC0402_25]
R931  100K  [RC0402_25]
R932  100K  [RC0402_25]
R933  100K  [RC0402_25]
R934  100K  [RC0402_25]
R935  100K  [RC0402_25]
R936  100K  [RC0402_25]
R937  100K  [RC0402_25]
R938  0  [RC0402_25]
R939  0  [RC0402_25]
R943  100K  [RC0402_25]
U561  PF8100  [qfn56_0p5_8p1x8p1_ep5p1]  (sections A,B,C)
sheet P07_PS_VDD
C24  22uF  [CC0805_OV]
C25  0.1UF  [CC0402_25]
C26  0.1UF  [CC0402_25]
C27  180uF  [cce6p8x6p8]
C28  22uF  [CC0805_OV]
C36  0.1UF  [CC0402_25]
C113  0.1UF  [CC0402_25]
C114  100UF  [CC1206_OV]
C115  100UF  [CC1206_OV]
C116  100UF  [CC1206_OV]
C118  100UF  [CC1206_OV]
C119  470uF  [CC7343-31]
C120  470uF  [CC7343-31]
C122  100PF  [CC0402_25]
C125  10uF  [CC0402_25]
C126  0.1UF  [CC0402_25]
C127  56PF  [CC0402_25]
C128  560PF  [CC0402_25]
C1334  0.1UF  [CC0402_25]
C1335  0.1UF  [CC0402_25]
C1472  0.022UF  [CC0402_25]
FL32  1.5uF  [CC_NFM41P_1806]
J8  HDR_1X2  [hdr1x2_50mil]
L9  0.33uH  [ind2_744308033]
R13  1  [RC0402_25]
R15  0  [RC0402_25]
R52  10.0  [RC0402_25]
R55  10.0K  [RC0402_25]
R56  255K  [RC0402_25]
R59  20K  [RC0402_25]
R60  60.4K  [RC0402_25]
R62  0  [RC0402_25]
R64  10.0  [RC0402_25]
R66  4.7K  [RC0402_25]
R67  30.1K  [RC0402_25]
R887  0  [RC0402_25]
R888  10.0  [RC0402_25]
R889  10.0  [RC0402_25]
R890  0.001  [res4_7p1X6p9_sm]
R893  0  [RC0402_25]
R894  0  [RC0402_25]
R895  0  [RC0402_25]
R896  0  [RC0402_25]
R897  0  [RC0402_25]
R898  0  [RC0402_25]
R899  0  [RC0402_25]
TP116  TP_PTH  [TP_PTH]
TP117  TP_PTH  [TP_PTH]
U557  LTC7150S  [bga42_0p8_5x6]
U558  INA220AIDGST  [MSOP_10_0P5_3X3]
sheet P08_CPU POWER1
C148  0.1uF  [CC0201]
C149  0.1uF  [CC0201]
C151  2.2UF  [CC0402_25]
C152  0.1uF  [CC0201]
C153  0.1uF  [CC0201]
C155  2.2UF  [CC0402_25]
C156  0.1uF  [CC0201]
C157  0.1uF  [CC0201]
C159  2.2UF  [CC0402_25]
C160  0.1uF  [CC0201]
C161  22UF  [CC0603_OV]
C162  0.1uF  [CC0201]
C163  0.1uF  [CC0201]
C164  0.1uF  [CC0201]
C165  0.1uF  [CC0201]
C166  22UF  [CC0603_OV]
C167  22UF  [CC0603_OV]
C168  22UF  [CC0603_OV]
C169  22UF  [CC0603_OV]
C170  22UF  [CC0603_OV]
C171  22UF  [CC0603_OV]
C172  22UF  [CC0603_OV]
C173  22UF  [CC0603_OV]
C174  22UF  [CC0603_OV]
C175  22UF  [CC0603_OV]
C176  22UF  [CC0603_OV]
C180  470uF  [CC7343-31]
C181  0.1uF  [CC0201]
C182  0.1uF  [CC0201]
C183  0.1uF  [CC0201]
C184  0.1uF  [CC0201]
C185  0.1uF  [CC0201]
C186  0.1uF  [CC0201]
C187  0.1uF  [CC0201]
C188  0.1uF  [CC0201]
C189  1500PF  [CC0201]
C190  1500PF  [CC0201]
C191  1500PF  [CC0201]
C193  0.1uF  [CC0201]
C194  0.1uF  [CC0201]
C195  0.1uF  [CC0201]
C196  0.1uF  [CC0201]
C197  0.1uF  [CC0201]
C198  0.1uF  [CC0201]
C199  0.1uF  [CC0201]
C200  0.1uF  [CC0201]
C201  0.1uF  [CC0201]
C202  0.1uF  [CC0201]
C203  1500PF  [CC0201]
C204  1500PF  [CC0201]
C205  1500PF  [CC0201]
C206  0.1uF  [CC0201]
C207  0.1uF  [CC0201]
C208  0.1uF  [CC0201]
C209  0.1uF  [CC0201]
C210  0.1uF  [CC0201]
C211  0.1uF  [CC0201]
C212  0.1uF  [CC0201]
C213  0.1uF  [CC0201]
C214  1500PF  [CC0201]
C215  1500PF  [CC0201]
C216  1500PF  [CC0201]
C217  1500PF  [CC0201]
C218  1500PF  [CC0201]
C219  0.1uF  [CC0201]
C220  0.1uF  [CC0201]
C221  0.1uF  [CC0201]
C222  0.1uF  [CC0201]
C223  0.1uF  [CC0201]
C224  0.1uF  [CC0201]
C225  0.1uF  [CC0201]
C226  0.1uF  [CC0201]
C227  0.1uF  [CC0201]
C228  0.1uF  [CC0201]
C229  0.1uF  [CC0201]
FL3  NFM18PC225B1A3  [cc0603_nfm18pc]
FL4  NFM18PC225B1A3  [cc0603_nfm18pc]
FL5  NFM18PC225B1A3  [cc0603_nfm18pc]
J9  HDR_1X2  [hdr1x2_50mil]
R964  100  [RC0201]
sheet P20_SD_SPI_MIKRO_CLICK
U14  LS1046ASE8T1A/LS1043XXXXX  [BGA780_0P8_23X23MM]  (sections A,B,C,D,E,F,G,H,I,J,K,L,M,N,O,P,Q)

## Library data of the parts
BH5-BH8 = MOUNT_HOLE: MOUNTING HOLE DRILL 126 PAD 244 PLATED TH, no part to order; AGILE_PN: 280-76195; CAD_APPROVED: Yes; HEIGHT: 0MM; MFG_NAME01: N/A; MFG_PN01: N/A; ROHS: Yes
C5 = CAP_POL: CAP ALEL 330uF 16V 20% -- SMD; AGILE_PN: 150-78783; CAD_APPROVED: Yes; HEIGHT: 10.5 MM; MFG_NAME01: LELON ELECTRONICS CORP; MFG_PN01: VE-331M1CTR-0810; ROHS: Yes; Tolerance: 20%; VOLTAGE: 16V
C12 C22 C25 C26 C30 C36 C113 C1330 C1344 C1348 C1470 C1581 = CAP_NP: CAP CER 0.1UF 25V 10% X5R 0402; AGILE_PN: 150-80045; CAD_APPROVED: Yes; FPLIST: CC0402_25,CC0402_HD,0402_CC; HEIGHT: 0.55MM; MFG_NAME01: Samsung Electro Mechanics; MFG_PN01: CL05A104KA5NNNC; ROHS: Yes; Tolerance: 10%; VOLTAGE: 25V
C14 C21 C1332 = CAP_NP: CAP CER 4.7UF 25V 10% X7R 0805; AGILE_PN: 150-75837; CAD_APPROVED: Yes; FPLIST: CC0805_OV,CC0805,0805_CC; HEIGHT: 1.4MM; MFG_NAME01: CAPAX TECHNOLOGIES INC.; MFG_PN01: 0805X475K250SNT; ROHS: Yes; Tolerance: 10%; VOLTAGE: 25V
C18 = CAP_NP: CAP CER 0.01UF 50V 10% X7R 0402; AGILE_PN: 150-30114; CAD_APPROVED: Yes; FPLIST: CC0402_25,CC0402_HD,0402_CC; HEIGHT: 0.74 MM; MFG_NAME01: WALSIN TECHNOLOGY CORP.; MFG_PN01: 0402B103K500CT; ROHS: Yes; Tolerance: 10%; VOLTAGE: 50V
C19 = CAP_NP: CAP CER 10pF 50V 5% C0G AEC-Q200 0402; AGILE_PN: 150-79023; CAD_APPROVED: Yes; FPLIST: CC0402_25,CC0402_HD,0402_CC; HEIGHT: 0.55MM; MFG_NAME01: MURATA; MFG_PN01: GCM1555C1H100JA16; ROHS: Yes; Tolerance: 5%; VOLTAGE: 50V
C20 = CAP_NP: CAP CER 47uF 10V 20% X5R 0805; AGILE_PN: 150-78979; CAD_APPROVED: Yes; FPLIST: CC0805_OV,CC0805,0805_CC; HEIGHT: 1.45 MM; MFG_NAME01: TDK; MFG_PN01: C2012X5R1A476M125AC; ROHS: Yes; Tolerance: 20%; VOLTAGE: 10V
C29 = CAP_NP: CAP CER 22uF 25V 20% X5R 0805; AGILE_PN: 150-79304; CAD_APPROVED: Yes; FPLIST: CC0805_OV,CC0805,0805_CC; HEIGHT: 1.45MM; MFG_NAME01: MURATA; MFG_PN01: GRM21BR61E226ME44; ROHS: Yes; ROOM: 12VIN; TOL: 20%; Tolerance: 20%; VOLTAGE: 25V
C31 C1587 = CAP_NP: CAP CER 22uF 25V 20% X5R 0805; AGILE_PN: 150-79304; CAD_APPROVED: Yes; FPLIST: CC0805_OV,CC0805,0805_CC; HEIGHT: 1.45MM; MFG_NAME01: MURATA; MFG_PN01: GRM21BR61E226ME44; ROHS: Yes; Tolerance: 20%; VOLTAGE: 25V
C32 = CAP_NP: CAP CER 0.01UF 50V 10% X7R 0402; AGILE_PN: 150-30114; CAD_APPROVED: Yes; FPLIST: CC0402_25,CC0402_HD,0402_CC; HEIGHT: 0.74 MM; MFG_NAME01: WALSIN TECHNOLOGY CORP.; MFG_PN01: 0402B103K500CT; ROHS: Yes; SIGNAL_MODEL: DEFAULT_CAPACITOR_10000pF_2_1; Tolerance: 10%; VOLTAGE: 50V
C1331 = CAP_POL: CAP TANT 22UF 16V 10% -- 3528-21; AGILE_PN: 150-78521; CAD_APPROVED: Yes; HEIGHT: 2.1MM; MFG_NAME01: AVX; MFG_PN01: TAJB226K016RNJ; ROHS: Yes; Tolerance: 10%; VOLTAGE: 16V
C1333 C1547-C1549 = CAP_NP: CAP CER 1uF 25V 10% X5R 0402; AGILE_PN: 150-80001; CAD_APPROVED: Yes; FPLIST: CC0402_25,CC0402_HD,0402_CC; HEIGHT: 0.55MM; MFG_NAME01: MURATA; MFG_PN01: GRM155R61E105KA12; ROHS: Yes; Temp_Range: -55°C to +85°C; Tolerance: 10%; VOLTAGE: 25 V
C1337 C1338 = CAP_POL: CAP POSCAP ESR0.035 OHM 220uF 6.3V 20% 3528; AGILE_PN: 150-80458; CAD_APPROVED: Yes; HEIGHT: 2.0 MM; MFG_NAME01: PANASONIC; MFG_PN01: 6TPE220MAZB; ROHS: Yes; Temp_Range: -55°C to +105°C; Tolerance: ±20%; VOLTAGE: 6.3V
C1339 C1340 = CAP_NP: CAP CER 47uF 10V 20% X5R 0805; AGILE_PN: 150-78979; CAD_APPROVED: Yes; FPLIST: CC0805_OV,CC0805,0805_CC; HEIGHT: 1.45 MM; MFG_NAME01: TDK; MFG_PN01: C2012X5R1A476M125AC; ROHS: Yes; SIGNAL_MODEL: DEFAULT_CAPACITOR_2.2e+07pF_2_1; Tolerance: 20%; VOLTAGE: 10V
C1341 = CAP_NP: CAP CER 47PF 16V 10% X7R 0402; AGILE_PN: 150-75656; CAD_APPROVED: Yes; FPLIST: CC0402_25,CC0402_HD,0402_CC; HEIGHT: 0.55 MM; MFG_NAME01: SMEC; MFG_PN01: MCCA470K0NRTF; ROHS: Yes; Tolerance: 10%; VOLTAGE: 16V
C1342 = CAP_NP: CAP CER 1uF 25V 10% X5R 0402; AGILE_PN: 150-80001; ASSY_OPT: DNP; CAD_APPROVED: Yes; FPLIST: CC0402_25,CC0402_HD,0402_CC; HEIGHT: 0.55MM; MFG_NAME01: MURATA; MFG_PN01: GRM155R61E105KA12; ROHS: Yes; Temp_Range: -55°C to +85°C; Tolerance: 10%; VOLTAGE: 25 V
C1343 = CAP_NP: CAP CER 150pF 50V 10% X7R 0402; AGILE_PN: 150-79481; CAD_APPROVED: Yes; FPLIST: CC0402_25,CC0402_HD,0402_CC; HEIGHT: 0.56MM; MFG_NAME01: AVX; MFG_PN01: 04025C151KAT2A; ROHS: Yes; Tolerance: 10%; VOLTAGE: 50V
C1345 C1347 C1468 C1469 = CAP_NP: CAP CER 22uF 25V 20% X5R AEC-Q200 0805; AGILE_PN: 150-79697; CAD_APPROVED: Yes; FPLIST: CC0805_OV,CC0805,0805_CC; HEIGHT: 1.45MM; MFG_NAME01: MURATA; MFG_PN01: GRT21BR61E226ME13; ROHS: Yes; SIGNAL_MODEL: DEFAULT_CAPACITOR_2.2e+07pF_2_1; Tolerance: 20%; VOLTAGE: 25V
C27 C1346 = CAP_POL: CAP ALEL ESR 22mOHMS 180uF 16V 20% RADIAL; AGILE_PN: 150-80417; CAD_APPROVED: Yes; HEIGHT: 6.0MM; MFG_NAME01: Nichicon; MFG_PN01: RSA1C181MCN1GS; ROHS: Yes; Temp_Range: -55C to +105C; VOLTAGE: 2.5-35V
C1471 = CAP_NP: CAP CER 22pF 50V 5% C0G AEC-Q200 0402; AGILE_PN: 150-79024; ASSY_OPT: DNP; CAD_APPROVED: Yes; FPLIST: CC0402_25,CC0402_HD,0402_CC; HEIGHT: 0.55MM; MFG_NAME01: MURATA; MFG_PN01: GCM1555C1H220JA16; ROHS: Yes; Tolerance: 5%; VOLTAGE: 50V
D6 = ZDIODE: DIODE ZNR -- 15V 0.5W SOD123; AGILE_PN: 480-77678; CAD_APPROVED: Yes; Function: Power; HEIGHT: 1.35MM; MFG_NAME01: On Semiconductor; MFG_PN01: MMSZ5245BT1G; ROHS: Yes
F2 = FUSE_RST: FUSE CKTBR FAST 8A 32V 1206; AGILE_PN: 510-77879; CAD_APPROVED: Yes; HEIGHT: 0.8639 MM; MFG_NAME01: LITTELFUSE; MFG_PN01: 0437008.WR; ROHS: Yes
FL2 FL31 FL32 = EMIFILTER_CC: CAP FILTER EMI 1.5uF 25V 20% -- 1806; AGILE_PN: 150-79370; CAD_APPROVED: Yes; HEIGHT: 1.2 MM; MFG_NAME01: Murata; MFG_PN01: NFM41PC155B1E3; ROHS: Yes; Tolerance: 20%; VOLTAGE: 25V
J1 = DC_POWER_JACK_063BH: CON 2 PWR JACK 2.0MM 2.1 MM RA TH 236MIL SP 362H NI 118L; AGILE_PN: 210-80341; CAD_APPROVED: Yes; HEIGHT: 9.2MM; MFG_NAME01: CUI INC; ROHS: Yes
J75 = CONN_HDR_2X1: HDR 1X2 TH 100MIL SP 339H AU 98L; AGILE_PN: 210-81490; CAD_APPROVED: Yes; HEIGHT: 8.59MM; MFG_NAME01: ANYTRONIC CORPORATION LIMITED; MFG_PN01: 0901S0202011N9T-31RF; ROHS: Yes; SILK: CPU_FAN; Temp_Range: -55°C to +105°C
L2 = CHOKE_4P: IND CHK 6uH 400OHM@10MHZ 10A -- SMT; AGILE_PN: 180-78066; CAD_APPROVED: Yes; HEIGHT: 9.4 MM; MFG_NAME01: murata; MFG_PN01: PLT10HH401100PNB; PART_TYPE: COIL; ROHS: Yes
L515 = INDUCTOR: IND PWR 2.2uH@100kHz 3.5A 20% AEC-Q200 SMT; AGILE_PN: 180-78608; CAD_APPROVED: Yes; HEIGHT: 2.1MM; MFG_NAME01: COILCRAFT; MFG_PN01: XFL4020-222ME; PART_TYPE: INDUCTOR\POWER; ROHS: Yes; TOL: 20%; Temp_Range: -40C to +125C; Tolerance: 20%
L516 = INDUCTOR: IND PWR 0.82uH@1MHz 20A 20% AEC-Q200 SMD; AGILE_PN: 180-78853; CAD_APPROVED: Yes; HEIGHT: 6.1MM; MFG_NAME01: COILCRAFT; MFG_PN01: XEL6060-821ME; PART_TYPE: INDUCTOR\POWER; ROHS: Yes; Temp_Range: -40 to +125C; Tolerance: 20%
R5 = RES: RES MF 1.0K 1/16W 1% 0402; AGILE_PN: 470-76037; ASSY_OPT: DNP; CAD_APPROVED: Yes; FPLIST: RC0402_25,RC0402_HD,RC0402_X2,0402_CC; HEIGHT: 0.4MM; MFG_NAME01: YAGEO AMERICA; MFG_PN01: RC0402FR-071KL; PRIORITY_PN: 006-00553; ROHS: Yes; ROOM: DDR_PS; Tolerance: 1%
R6 R887 R899 R904 R938 = RES: RES MF ZERO OHM 1/10W -- 0402; AGILE_PN: 470-79965; CAD_APPROVED: Yes; FPLIST: RC0402_25,RC0402_HD,RC0402_X2,0402_CC; HEIGHT: 0.4MM; MFG_NAME01: Panasonic; MFG_PN01: ERJ-2GE0R00X; ROHS: Yes; ROOM: VDD_GVDD_PS; TOL: 5%; VOLTAGE: 1/10W
R7 = RES: RES MF 1.0M 1/16W 1% AEC-Q200 0402; AGILE_PN: 470-30000; CAD_APPROVED: Yes; FPLIST: RC0402_25,RC0402_HD,0402_CC; HEIGHT: 0.4MM; MFG_NAME01: VISHAY INTERTECHNOLOGY; MFG_PN01: CRCW04021M00FKED; ROHS: Yes; Temp_Range: -55°C ~ 155°C; Tolerance: 1%
R10 = RES: RES MF 1.0K 1/16W 1% 0402; AGILE_PN: 470-76037; CAD_APPROVED: Yes; FPLIST: RC0402_25,RC0402_HD,RC0402_X2,0402_CC; HEIGHT: 0.4MM; MFG_NAME01: YAGEO AMERICA; MFG_PN01: RC0402FR-071KL; PRIORITY_PN: 006-00553; ROHS: Yes; ROOM: DDR_PS; Tolerance: 1%
R11 = RES: RES MF 18.2K 1/10W 1% AEC-Q200 0402; AGILE_PN: 470-82006; CAD_APPROVED: Yes; FPLIST: RC0402_25,RC0402_HD,0402_CC; HEIGHT: 0.45MM; MFG_NAME01: KOA SPEER; MFG_PN01: RK73H1ETTP1822F; ROHS: Yes; Temp_Range: -55C to +155C; Tolerance: 1%
R886 = RES: RES MF 182K 1/10W 1% AEC-Q200 0402; AGILE_PN: 470-31089; CAD_APPROVED: Yes; FPLIST: RC0402_25,RC0402_HD,0402_CC; HEIGHT: 0.40 MM; MFG_NAME01: KOA SPEER; MFG_PN01: RK73H1ETTP1823F; ROHS: Yes; Temp_Range: -55C to +155C; Tolerance: 1%
R900 R901 R906 R927-R929 R931-R937 R943 = RES: RES MF 100K 1/16W 1% 0402; AGILE_PN: 470-76240; CAD_APPROVED: Yes; FPLIST: RC0402_25,RC0402_HD,0402_CC; HEIGHT: 0.4MM; MFG_NAME01: NIC COMPONENTS CORP; MFG_PN01: NRCL04F1003TRF; ROHS: Yes; Tolerance: 1%
R902 = RES: RES MF 22.1K 1/10W 1% AEC-Q200 0402; AGILE_PN: 470-30984; CAD_APPROVED: Yes; FPLIST: RC0402_25,RC0402_HD,0402_CC; HEIGHT: 0.40 MM; MFG_NAME01: KOA SPEER; MFG_PN01: RK73H1ETTP2212F; ROHS: Yes; Temp_Range: -55C to +155C; Tolerance: 1%
R903 = RES: RES MF 17.8K  1/16W 1% 0402; AGILE_PN: 470-30973; CAD_APPROVED: Yes; FPLIST: RC0402_25,RC0402_HD,0402_CC; HEIGHT: 0.40 MM; MFG_NAME01: BOURNS INC.; MFG_PN01: CR0402-FX-1782GLF; ROHS: Yes; Temp_Range: -55C to +155C; Tolerance: 1%
R905 = RES: RES MF 9.31K 1/10W 1% AEC-Q200 0402; AGILE_PN: 470-30944; CAD_APPROVED: Yes; FPLIST: RC0402_25,RC0402_HD,0402_CC; HEIGHT: 0.40 MM; MFG_NAME01: KOA SPEER; MFG_PN01: RK73H1ETTP9311F; ROHS: Yes; Temp_Range: -55C to +155C; Tolerance: 1%
R907 = RES: RES MF 10K 1/5W 1% AEC-Q200 0402; AGILE_PN: 470-80881; CAD_APPROVED: Yes; FPLIST: RC0402_25,RC0402_HD,0402_CC; HEIGHT: 0.4MM; MFG_NAME01: VISHAY INTERTECHNOLOGY; MFG_PN01: CRCW040210K0FKEDHP; ROHS: Yes; Temp_Range: -55&#8451; to 155&#8451;; Tolerance: 1%
S2 S3 = DO57: ANCHOR FOR HEAT SINK 10-THMA-01; AGILE_PN: 901-76137; CAD_APPROVED: Yes; HEIGHT: 7.83mm; MFG_NAME01: AAVID THERMALLOY; MFG_PN01: 125700D00000G; ROHS: Yes
TP94 TP95 = TEST_POINT: TEST POINT BLK 70X220 MIL TH; AGILE_PN: 210-30155; CAD_APPROVED: Yes; HEIGHT: 5.6MM; MFG_NAME01: Keystone Electronics; ROHS: Yes; ROOM: CS; SILK: GND
U1 = LT8609S_16P_EP: IC LIN DC/DC SYNC BUCK 3-42V 2A QFN16; AGILE_PN: 315-81632; CAD_APPROVED: Yes; HEIGHT: 1.03MM; MFG_NAME01: LINEAR TECHNOLOGY; MFG_PN01: LT8609SEV#PBF; ROHS: Yes; Temp_Range: -40C to +125C
U560 = LT8642SEV_LQFN24: IC LIN DC/DC SYNC BUCK 2.8-18V 10A LQFN24; AGILE_PN: 315-82128; CAD_APPROVED: Yes; HEIGHT: 1.03MM; MFG_NAME01: ANALOG DEVICES; MFG_PN01: LT8642SEV#PBF; ROHS: Yes; Temp_Range: -40°C to 125°C
C161 C1475 C1476 C1520 C1521 C1524 C1525 C1530 C1531 C1533 C1534 C1536 C1537 = CAP_NP: CAP CER 22UF 6.3V 20% X5R 0603; AGILE_PN: 150-78467; CAD_APPROVED: Yes; FPLIST: CC0603_OV,CC0603,0603_CC; HEIGHT: 1MM; MFG_NAME01: Samsung; MFG_PN01: CL10A226MQ8NRNE; ROHS: Yes; SIGNAL_MODEL: DEFAULT_CAPACITOR_2.2e+07pF_2_1; Tolerance: 20%; VOLTAGE: 6.3V; WVDC: 6.3V
C1481 C1489-C1494 = CAP_NP: CAP CER 4.7UF 10V 20% X5R 0402; AGILE_PN: 150-79667; CAD_APPROVED: Yes; FPLIST: CC0402_25,CC0402_HD,0402_CC; HEIGHT: 0.65MM; MFG_NAME01: Murata; MFG_PN01: GRM155R61A475MEAA; ROHS: Yes; SIGNAL_MODEL: DEFAULT_CAPACITOR_4.7e+06pF_2_1; Temp_Range: -55 to 85; Tolerance: 20%; VOLTAGE: 10V; WVDC: 10V
C1495 C1523 C1526 C1532 C1535 C1538 C1544 = CAP_NP: CAP CER 0.1UF 25V 10% X5R 0402; AGILE_PN: 150-80045; CAD_APPROVED: Yes; FPLIST: CC0402_25,CC0402_HD,0402_CC; HEIGHT: 0.55MM; MFG_NAME01: Samsung Electro Mechanics; MFG_PN01: CL05A104KA5NNNC; ROHS: Yes; SIGNAL_MODEL: DEFAULT_CAPACITOR_100000pF_2_1; TOL: 10%; Tolerance: 10%; VOLTAGE: 25V; WVDC: 16V
C1540 C1545 = CAP_NP: CAP CER 1uF 25V 10% X5R 0402; AGILE_PN: 150-80001; CAD_APPROVED: Yes; FPLIST: CC0402_25,CC0402_HD,0402_CC; HEIGHT: 0.55MM; MFG_NAME01: MURATA; MFG_PN01: GRM155R61E105KA12; ROHS: Yes; SIGNAL_MODEL: DEFAULT_CAPACITOR_1e+06pF_2_1; Temp_Range: -55°C to +85°C; Tolerance: 10%; VOLTAGE: 25 V; WVDC: 10V
C1542 = CAP_NP: CAP CER 1uF 25V 10% X5R 0402; AGILE_PN: 150-80001; CAD_APPROVED: Yes; FPLIST: CC0402_25,CC0402_HD,0402_CC; HEIGHT: 0.55MM; MFG_NAME01: MURATA; MFG_PN01: GRM155R61E105KA12; ROHS: Yes; SIGNAL_MODEL: DEFAULT_CAPACITOR_1e+06pF_2_1; TOL: 10%; Temp_Range: -55°C to +85°C; Tolerance: 10%; VOLTAGE: 25 V; WVDC: 10V
C1546 = CAP_NP: CAP CER 0.22uF 6.3V 10% X5R 0201; AGILE_PN: 150-79474; CAD_APPROVED: Yes; FPLIST: CC0201,CC0201_HD,0201_CC,cc_0201_cir; HEIGHT: 0.33MM; MFG_NAME01: MURATA; MFG_PN01: GRM033R60J224KE15D; ROHS: Yes; Tolerance: 10%; VOLTAGE: 6.3V
C151 C155 C159 C1550 = CAP_NP: CAP CER 2.2UF 10V 20% X5R 0402; AGILE_PN: 150-79665; CAD_APPROVED: Yes; FPLIST: CC0402_25,CC0402_HD,0402_CC; HEIGHT: 0.55 MM; MFG_NAME01: Murata; MFG_PN01: GRM155R61A225ME95; ROHS: Yes; Tolerance: 20%; VOLTAGE: 10V
C1551-C1554 = CAP_NP: CAP CER 4.7UF 10V 20% X5R 0402; AGILE_PN: 150-79667; CAD_APPROVED: Yes; FPLIST: CC0402_25,CC0402_HD,0402_CC; HEIGHT: 0.65MM; MFG_NAME01: Murata; MFG_PN01: GRM155R61A475MEAA; ROHS: Yes; SIGNAL_MODEL: DEFAULT_CAPACITOR_4.7e+06pF_2_1; TOL: 10%; Temp_Range: -55 to 85; Tolerance: 20%; VOLTAGE: 10V; WVDC: 10V
L531-L533 L535-L537 = INDUCTOR: IND PWR 1.0uH@1MHZ 4.7A 20% AEC-Q200 SMD; AGILE_PN: 180-78525; CAD_APPROVED: Yes; HEIGHT: 1.2MM; MFG_NAME01: TDK; MFG_PN01: TFM252012ALMA1R0MTAA; PART_TYPE: INDUCTOR\POWER; ROHS: Yes; Tolerance: 20%
R55 R930 = RES: RES MF 10.0K 1/16W 1% 0402; AGILE_PN: 470-80574; CAD_APPROVED: Yes; FPLIST: RC0402_25,RC0402_HD,0402_CC; HEIGHT: 0.4MM; MFG_NAME01: WALSIN TECHNOLOGY CORP.; MFG_PN01: WR04X1002FTL; ROHS: Yes; Tolerance: 1%
R15 R939 = RES: RES MF ZERO OHM 1/10W -- 0402; AGILE_PN: 470-79965; ASSY_OPT: DNP; CAD_APPROVED: Yes; FPLIST: RC0402_25,RC0402_HD,RC0402_X2,0402_CC; HEIGHT: 0.4MM; MFG_NAME01: Panasonic; MFG_PN01: ERJ-2GE0R00X; ROHS: Yes; ROOM: VDD_GVDD_PS; TOL: 5%; VOLTAGE: 1/10W
U561 = PC33PF8100A0ES_QFN56: IC POWER MANAGEMENT 2.7-5.5V AEC-Q100 QFN56; AGILE_PN: TMP-WF-35178; CAD_APPROVED: Yes; HEIGHT: 1 MM; MFG_NAME01: NXP SEMICONDUCTORS; MFG_PN01: PC33PF8100EAES; PRE_APN: 315-82184; ROHS: Yes; Temp_Range: -40°C to +105°C
C24 C28 = CAP_NP: CAP CER 22uF 25V 20% X5R 0805; AGILE_PN: 150-79304; CAD_APPROVED: Yes; FPLIST: CC0805_OV,CC0805,0805_CC; HEIGHT: 1.45MM; MFG_NAME01: MURATA; MFG_PN01: GRM21BR61E226ME44; ROHS: Yes; SIGNAL_MODEL: DEFAULT_CAPACITOR_2.2e+07pF_2_1; Tolerance: 20%; VOLTAGE: 25V
C114-C116 C118 = CAP_NP: CAP CER 100UF 6.3V 20% X5R 1206; AGILE_PN: 150-77574; CAD_APPROVED: Yes; FPLIST: CC1206_OV,CC1206,1206_CC; HEIGHT: 1.9 MM; MFG_NAME01: Murata; MFG_PN01: GRM31CR60J107ME39L; ROHS: Yes; ROOM: VDD_GVDD_PS; Tolerance: 20%; VOLTAGE: 6.3V
C119 C120 C180 = CAP_POL: CAP POLM AL ESR 0.006 OHMS 470uF 2V 20% 7343-21; AGILE_PN: 150-78900; CAD_APPROVED: Yes; HEIGHT: 2.1MM; MFG_NAME01: PANASONIC; MFG_PN01: EEFSX0D471XE; ROHS: Yes; Tolerance: 20%; VOLTAGE: 2V
C122 = CAP_NP: CAP CER 100PF 50V 5% X7R 0402; AGILE_PN: 150-78133; ASSY_OPT: DNP; CAD_APPROVED: Yes; FPLIST: CC0402_25,CC0402_HD,0402_CC; HEIGHT: 0.6MM; MFG_NAME01: CAL-CHIP; MFG_PN01: GMC04X7R101J50NT-LF; ROHS: Yes; TOL: 5%; Tolerance: 5%
C125 = CAP_NP: CAP CER 10UF 6.3V 20% X6S 0402; AGILE_PN: 150-80079; CAD_APPROVED: Yes; FPLIST: CC0402_25,CC0402_HD,0402_CC; HEIGHT: 0.7MM; MFG_NAME01: MURATA; MFG_PN01: GRM155C80J106ME11D; ROHS: Yes; Temp_Range: -55 to 105&#8451;; Tolerance: 20%; VOLTAGE: 6.3V
C126 C1334 = CAP_NP: CAP CER 0.1UF 25V 10% X5R 0402; AGILE_PN: 150-80045; CAD_APPROVED: Yes; FPLIST: CC0402_25,CC0402_HD,0402_CC; HEIGHT: 0.55MM; MFG_NAME01: Samsung Electro Mechanics; MFG_PN01: CL05A104KA5NNNC; ROHS: Yes; SIGNAL_MODEL: DEFAULT_CAPACITOR_100000pF_2_1; TOL: 10%; Tolerance: 10%; VOLTAGE: 25V
C127 = CAP_NP: CAP CER 56PF 50V 5% C0G 0402; AGILE_PN: 150-30269; CAD_APPROVED: Yes; FPLIST: CC0402_25,CC0402_HD,0402_CC; HEIGHT: 0.55 MM; MFG_NAME01: MURATA; MFG_PN01: GRM1555C1H560JA01D; ROHS: Yes; ROOM: VDD_GVDD_PS; Tolerance: 5%; VOLTAGE: 50V
C128 = CAP_NP: CAP CER 560pF 50V 1% C0G 0402; AGILE_PN: 150-80174; CAD_APPROVED: Yes; FPLIST: CC0402_25,CC0402_HD,0402_CC; HEIGHT: 0.55MM; MFG_NAME01: MURATA; MFG_PN01: GRM1555C1H561FA01D; ROHS: Yes; Temp_Range: -55C to +125C; Tolerance: 1%; VOLTAGE: 50V
C1335 = CAP_NP: CAP CER 0.1UF 25V 10% X5R 0402; AGILE_PN: 150-80045; CAD_APPROVED: Yes; FPLIST: CC0402_25,CC0402_HD,0402_CC; HEIGHT: 0.55MM; MFG_NAME01: Samsung Electro Mechanics; MFG_PN01: CL05A104KA5NNNC; ROHS: Yes; TOL: 10%; Tolerance: 10%; VOLTAGE: 25V
C1472 = CAP_NP: CAP CER 0.022UF 16V 10% X7R 0402; AGILE_PN: 150-30293; CAD_APPROVED: Yes; FPLIST: CC0402_25,CC0402_HD,0402_CC; HEIGHT: 0.56MM; MFG_NAME01: AVX; MFG_PN01: 0402YC223KAT2A; ROHS: Yes; Tolerance: 10%; VOLTAGE: 16V
J8 = CONN_HDR_2X1: HDR 1X2 TH 50MIL SP 165H AU 91L; AGILE_PN: 210-80212; CAD_APPROVED: Yes; HEIGHT: 4.2MM; MFG_NAME01: SULLINS ELECTRONICS CORP; MFG_PN01: GRPB021VWVN-RC; ROHS: Yes; SILK: VDD_SEL
L9 = INDUCTOR: IND PWR 0.33uH@100KHZ 27A 20% SMD; AGILE_PN: 180-77944; CAD_APPROVED: Yes; HEIGHT: 7MM; MFG_NAME01: WURTH ELEKTRONIK EISOS GMBH & CO. KG (ELECTRONIC & ELECTROMEHANICAL COMP); MFG_PN01: 744308033; PART_TYPE: INDUCTOR\POWER; ROHS: Yes; Tolerance: 20%
R13 = RES: RES MF 1 OHM 1/16W 1% AEC-Q200 0402; AGILE_PN: 470-80805; CAD_APPROVED: Yes; FPLIST: RC0402_25,RC0402_HD,0402_CC; HEIGHT: 0.4MM; MFG_NAME01: VISHAY INTERTECHNOLOGY; MFG_PN01: CRCW04021R00FKED; ROHS: Yes; Tolerance: 1%
R52 R64 R888 R889 = RES: RES MF 10.0 OHM 1/16W 1% 0402; AGILE_PN: 470-76090; CAD_APPROVED: Yes; FPLIST: RC0402_25,RC0402_HD,0402_CC; HEIGHT: 0.4MM; MFG_NAME01: BOURNS; MFG_PN01: CR0402-FX-10R0GLF; ROHS: Yes; Tolerance: 1%
R56 = RES: RES MF 255K 1/10W 1% AEC-Q200 0402; AGILE_PN: 470-31104; CAD_APPROVED: Yes; FPLIST: RC0402_25,RC0402_HD,0402_CC; HEIGHT: 0.40 MM; MFG_NAME01: KOA SPEER; MFG_PN01: RK73H1ETTP2553F; ROHS: Yes; Temp_Range: -55C to +155C; Tolerance: 1%
R59 = RES: RES MF 20K 1/16W 1% 0402; AGILE_PN: 470-76103; CAD_APPROVED: Yes; FPLIST: RC0402_25,RC0402_HD,0402_CC; HEIGHT: 0.4MM; MFG_NAME01: WALSIN TECHNOLOGY CORP.; MFG_PN01: WR04X2002FTL; ROHS: Yes; Tolerance: 1%
R60 = RES: RES MF 60.4K 1/10W 1% AEC-Q200 0402; AGILE_PN: 470-31036; CAD_APPROVED: Yes; FPLIST: RC0402_25,RC0402_HD,0402_CC; HEIGHT: 0.40 MM; MFG_NAME01: KOA SPEER; MFG_PN01: RK73H1ETTP6042F; ROHS: Yes; Temp_Range: -55C to +155C; Tolerance: 1%
R62 R894-R896 R898 = RES: RES MF ZERO OHM 1/10W -- 0402; AGILE_PN: 470-79965; CAD_APPROVED: Yes; FPLIST: RC0402_25,RC0402_HD,RC0402_X2,0402_CC; HEIGHT: 0.4MM; MFG_NAME01: Panasonic; MFG_PN01: ERJ-2GE0R00X; ROHS: Yes
R66 = RES: RES MF 4.70K 1/16W 1% 0402; AGILE_PN: 470-75418; CAD_APPROVED: Yes; FPLIST: RC0402_25,RC0402_HD,0402_CC; HEIGHT: 0.4mm; MFG_NAME01: WALSIN TECHNOLOGY CORP.; MFG_PN01: WR04X4701FTL; ROHS: Yes; Tolerance: 1%
R67 = RES: RES MF 30.1K 1/16W 1% 0402; AGILE_PN: 470-76217; CAD_APPROVED: Yes; FPLIST: RC0402_25,RC0402_HD,0402_CC; HEIGHT: 0.45 MM; MFG_NAME01: SMEC; MFG_PN01: RC73A2Z3012FTF; ROHS: Yes; Tolerance: 1%
R890 = RES_4PIN: RES MF 0.001 OHM 3W 1% 2726; AGILE_PN: 470-80370; CAD_APPROVED: Yes; HEIGHT: 3.2MM; MFG_NAME01: VISHAY INTERTECHNOLOGY; MFG_PN01: WSL27261L000FEA; ROHS: Yes
R893 R897 = RES: RES MF ZERO OHM 1/10W -- 0402; AGILE_PN: 470-79965; ASSY_OPT: DNP; CAD_APPROVED: Yes; FPLIST: RC0402_25,RC0402_HD,RC0402_X2,0402_CC; HEIGHT: 0.4MM; MFG_NAME01: Panasonic; MFG_PN01: ERJ-2GE0R00X; ROHS: Yes
TP116 = TestLoop: TEST POINT PAD 035-018MIL TH, NO PART TO ORDER; AGILE_PN: 210-77612; CAD_APPROVED: Yes; HEIGHT: 0.1 mm; MFG_NAME01: NOTACOMPONENT; MFG_PN01: NOTACOMPONENT; ROHS: Yes; SILK: +CPU_VDD_I
TP117 = TestLoop: TEST POINT PAD 035-018MIL TH, NO PART TO ORDER; AGILE_PN: 210-77612; CAD_APPROVED: Yes; HEIGHT: 0.1 mm; MFG_NAME01: NOTACOMPONENT; MFG_PN01: NOTACOMPONENT; ROHS: Yes; SILK: +CPU_VDD
U557 = LTC7150_BGA42: IC VREG SYNC STEP-DOWN 0.6-5.5V 20A 3.1-20V BGA42; AGILE_PN: 315-81406; CAD_APPROVED: Yes; HEIGHT: 1.5MM; MFG_NAME01: LINEAR TECHNOLOGY; MFG_PN01: LTC7150SEY#PBF; ROHS: Yes; Temp_Range: -40C to 125C
U558 = INA220AIDGST: IC CURRENT/POWER MONITOR 0-26V 3-5.5V MSOP10; AGILE_PN: 315-79035; CAD_APPROVED: Yes; FPLIST: msop_10_0p5_3x3,msop10_0p5_3p1x3p1_ipc; HEIGHT: 1.10MM; MFG_NAME01: TEXAS INSTRUMENTS; PRIORITY_PN: 051-INA220; ROHS: Yes; ROOM: I2C1_CH2; VOLTAGE: 3-5.5V
C148 C149 C152 C153 C156 C157 C160 C162-C165 C181-C188 C193-C202 C206-C213 C219-C229 = CAP_NP: CAP CER 0.1uF 16V 10% X5R 0201; AGILE_PN: 150-80059; CAD_APPROVED: Yes; FPLIST: CC0201,CC0201_HD,0201_CC; HEIGHT: 0.33MM; MFG_NAME01: MURATA; MFG_PN01: GRM033R61C104KE14D; ROHS: Yes; TOL: 10%; Temp_Range: -55 to +85°C; Tolerance: 10%; VOLTAGE: 16V
C166-C176 = CAP_NP: CAP CER 22UF 6.3V 20% X5R 0603; AGILE_PN: 150-78467; CAD_APPROVED: Yes; FPLIST: CC0603_OV,CC0603,0603_CC; HEIGHT: 1MM; MFG_NAME01: Samsung; MFG_PN01: CL10A226MQ8NRNE; ROHS: Yes; SIGNAL_MODEL: DEFAULT_CAPACITOR_2.2e+07pF_2_1; Tolerance: 20%; VOLTAGE: 6.3V
C189-C191 C203-C205 C214-C218 = CAP_NP: CAP CER 1500PF 10V 10% X5R 0201; AGILE_PN: 150-75466; CAD_APPROVED: Yes; FPLIST: CC0201,CC0201_HD,0201_CC; HEIGHT: 0.33MM; MFG_NAME01: MURATA; MFG_PN01: GRM033R61A152KA01D; ROHS: Yes; SIGNAL_MODEL: DEFAULT_CAPACITOR_1500pF_2_1; TOL: 10%; Tolerance: 10%; VOLTAGE: 10V
FL3-FL5 = NFM18PC225B1A3: CAP FILTER EMI 2.2uF 10V 20% -- 0603; AGILE_PN: 150-79428; CAD_APPROVED: Yes; HEIGHT: 0.9MM; MFG_NAME01: MURATA; MFG_PN01: NFM18PC225B1A3D; ROHS: Yes; ROOM: DUT_CLOSE; Temp_Range: -40 C to +85 C; Tolerance: 20%; VOLTAGE: 10V
J9 = CONN_HDR_2X1: HDR 1X2 TH 50MIL SP 165H AU 91L; AGILE_PN: 210-80212; CAD_APPROVED: Yes; HEIGHT: 4.2MM; MFG_NAME01: SULLINS ELECTRONICS CORP; MFG_PN01: GRPB021VWVN-RC; ROHS: Yes; SILK: TA_BB_VDD
R964 = RES: RES MF 100 OHM 1/20W 1% AEC-Q200 0201; AGILE_PN: 470-81361; CAD_APPROVED: Yes; FPLIST: RC0201,0201_CC; HEIGHT: 0.26 MM; MFG_NAME01: YAGEO AMERICA; MFG_PN01: AC0201FR-07100RL; ROHS: Yes; Temp_Range: -55&#8451; to 155&#8451;
U14 = LS1043_1046_SS: IC MCU LS1046 and LS1043 FBGA780; AGILE_PN: TMP-WF-33894; CAD_APPROVED: Yes; HEIGHT: 2.61/2.07MM; MFG_NAME01: NXP SEMICONDUCTORS; PRE_APN: 344-02328; ROHS: Yes

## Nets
1V0_F104: C1475.1 C1476.1 C1495.1 L531.1 U561.3(SW1FB) ; also on sheet 15
1V35: C1524.1 C1525.1 C1526.1 L533.1 U561.13(SW3FB) ; also on sheet 9
2V5: C160.1 C161.1 C1536.1 C1537.1 C1538.1 L537.1 U14.W6(TVDD) U561.38(SW7FB) ; also on sheet 10 11 15 18
3V3: C1334.1 C1337.1 C1338.1 C1339.1 C1340.1 C1341.1 C1470.1 C1481.1 C1489.1 C1490.1 C1491.1 C1492.1 C1493.1 C1494.1 C1542.1 C1544.1 C1547.1 C1548.1 C1549.1 FL5.1(IN_OUT) L516.2 R5.1 R10.1 R66.1 R900.1 R901.1 R904.1 R927.1 R928.1 R929.1 R931.2 R934.1 R936.1 U558.6(VCC) U561.4(SW1IN) U561.7(SW2IN) U561.8(SW3IN) U561.11(SW4IN) U561.17(LDO12IN) U561.26(LDO3IN) U561.27(LDO4IN) U561.32(SW5IN) U561.35(SW6IN) U561.37(SW7IN) U561.50(VIN) U561.54(VDDIO) ; also on sheet 9 13 14 16 17 18 19 20
3V3_EN: R906.2 R907.1 U560.17(EN/UV)
5V0: C19.2 C20.1 C21.1 C22.1 L515.2 R7.2 ; also on sheet 19 20
12V0: C5.1 C12.1 C14.1 C30.1 C31.1 C32.1 C1330.1 C1345.1 C1587.1 FL2.1(INPUT) FL31.1(INPUT) FL32.1(INPUT) J75.1 L2.2
12V0_FILTERED_PS_V1V0: C24.1 C25.1 C26.1 C27.1 C28.1 FL32.3(OUTPUT) R13.1 U557.C2(PVIN1) U557.C5(PVIN2) U557.C6(PVIN3) U557.D1(PVIN4) U557.D2(PVIN5) U557.D5(PVIN6) U557.D6(PVIN7)
12V0_FILTERED_PS_V3V3: C1346.1 C1347.1 C1348.1 C1468.1 C1469.1 C1581.1 FL31.3(OUTPUT) R906.1 U560.4(VIN1) U560.5(VIN2) U560.6(VIN3) U560.13(VIN4) U560.14(VIN5) U560.15(VIN6)
12V0_FILTERED_PS_V5V0: C1331.1 C1332.1 FL2.3(OUTPUT) U1.9(PVIN1) U1.10(PVIN2)
12V0_IN: F2.1 J1.1
12V0_IN_GND: C29.2 D6.A(ANODE) J1.2 L2.4
12V0_PS_F: C29.1 D6.C(CATHODE) F2.2 L2.1
GND: C5.2 C12.2 C14.2 C18.1 C20.2 C21.2 C22.2 C24.2 C25.2 C26.2 C27.2 C28.2 C30.2 C31.2 C32.2 C113.2 C114.2 C115.2 C116.2 C118.2 C119.2 C120.2 C125.2 C148.2 C149.2 C151.2 C152.2 C153.2 C155.2 C156.2 C157.2 C159.2 C160.2 C161.2 C162.2 C163.2 C164.2 C165.2 C166.2 C167.2 C168.2 C169.2 C170.2 C171.2 C172.2 C173.2 C174.2 C175.2 C176.2 C180.2 C181.2 C182.2 C183.2 C184.2 C185.2 C186.2 C187.2 C188.2 C189.2 C190.2 C191.2 C193.2 C194.2 C195.2 C196.2 C197.2 C198.2 C199.2 C200.2 C201.2 C202.2 C203.2 C204.2 C205.2 C206.2 C207.2 C208.2 C209.2 C210.2 C211.2 C212.2 C213.2 C214.2 C215.2 C216.2 C217.2 C218.2 C219.2 C220.2 C221.2 C222.2 C223.2 C224.2 C225.2 C226.2 C227.2 C228.2 C229.2 C1330.2 C1331.2 C1332.2 C1333.1 C1334.2 C1337.2 C1338.2 C1339.2 C1340.2 C1342.1 C1343.2 C1344.2 C1345.2 C1346.2 C1347.2 C1348.2 C1468.2 C1469.2 C1470.2 C1471.2 C1475.2 C1476.2 C1481.2 C1489.2 C1490.2 C1491.2 C1492.2 C1493.2 C1494.2 C1495.2 C1520.2 C1521.2 C1523.2 C1524.2 C1525.2 C1526.2 C1530.2 C1531.2 C1532.2 C1533.2 C1534.2 C1535.2 C1536.2 C1537.2 C1538.2 C1540.2 C1542.2 C1544.2 C1545.2 C1546.2 C1547.2 C1548.2 C1549.2 C1550.2 C1551.2 C1552.2 C1553.2 C1554.2 C1581.2 C1587.2 FL2.2A(GND) FL2.2B(GND) FL3.2(GND) FL4.2(GND) FL5.2(GND) FL31.2A(GND) FL31.2B(GND) FL32.2A(GND) FL32.2B(GND) J75.2 L2.3 R11.1 R64.2 R886.2 R887.2 R902.2 R903.2 R907.2 R930.2 R932.2 R933.2 R935.1 R943.2 R964.2 TP94.1 TP95.1 U1.3(GND1) U1.4(GND2) U1.7(NC) U1.8(GND3) U1.14(GND4) U1.17(GND5) U14.A2(GND001) U14.A5(GND002) U14.A21(GND003) U14.AA4(GND167) U14.AA5(SD_GND08) U14.AA7(SD_GND09) U14.AA9(SD_GND10) U14.AA12(SD_GND11) U14.AA14(GND168) U14.AA17(SD_GND12) U14.AA18(SD_GND13) U14.AA19(SD_GND14) U14.AA21(GND169) U14.AA24(GND170) U14.AB2(GND171) U14.AB7(SD_GND15) U14.AB9(SD_GND16) U14.AB12(GND172) U14.AB14(SD_GND17) U14.AB17(SD_GND18) U14.AB20(SD_GND19) U14.AB26(GND173) U14.AC5(SD_GND20) U14.AC6(SD_GND21) U14.AC8(SD_GND22) U14.AC10(SD_GND23) U14.AC11(SD_GND24) U14.AC15(SD_GND25) U14.AC16(SD_GND26) U14.AC18(SD_GND27) U14.AC19(SD_GND28) U14.AC21(GND174) U14.AC24(GND175) U14.AD2(GND176) U14.AD4(GND177) U14.AD5(SD_GND29) U14.AD7(SD_GND30) U14.AD9(SD_GND31) U14.AD12(SD_GND32) U14.AD14(SD_GND33) U14.AD17(SD_GND34) U14.AD20(SD_GND35) U14.AD26(GND178) U14.AE5(SD_GND36) U14.AE7(SD_GND37) U14.AE9(SD_GND38) U14.AE12(SD_GND39) U14.AE14(SD_GND40) U14.AE17(SD_GND41) U14.AE20(SD_GND42) U14.AE21(GND179) U14.AE24(GND180) U14.AF4(GND181) U14.AF6(SD_GND43) U14.AF7(SD_GND44) U14.AF8(SD_GND45) U14.AF9(SD_GND46) U14.AF10(SD_GND47) U14.AF11(SD_GND48) U14.AF15(SD_GND49) U14.AF16(SD_GND50) U14.AF17(SD_GND51) U14.AF18(SD_GND52) U14.AF19(SD_GND53) U14.AF21(GND182) U14.AF26(GND183) U14.AG1(GND184) U14.AG5(SD_GND54) U14.AG7(SD_GND55) U14.AG9(SD_GND56) U14.AG12(SD_GND57) U14.AG14(SD_GND58) U14.AG17(SD_GND59) U14.AG20(SD_GND60) U14.AG24(GND185) U14.AG26(GND186) U14.AH2(GND187) U14.AH5(SD_GND61) U14.AH7(SD_GND62) U14.AH9(SD_GND63) U14.AH12(SD_GND64) U14.AH14(SD_GND65) U14.AH17(SD_GND66) U14.AH20(SD_GND67) U14.AH21(GND188) U14.B3(GND004) U14.B4(GND005) U14.B7(GND006) U14.B10(GND007) U14.B13(GND008) U14.B16(GND009) U14.B19(GND010) U14.B21(GND011) U14.B24(GND012) U14.B26(GND013) U14.C1(GND014) U14.C2(GND015) U14.C5(GND016) U14.C21(GND017) U14.C27(GND018) U14.D3(GND019) U14.D4(GND020) U14.D7(GND021) U14.D9(GND022) U14.D12(GND023) U14.D15(GND024) U14.D18(GND025) U14.D21(GND026) U14.D24(GND027) U14.E1(GND028) U14.E2(GND029) U14.E5(GND030) U14.E21(GND031) U14.E26(GND032) U14.F3(GND033) U14.F4(GND034) U14.F7(GND035) U14.F14(GND036) U14.F16(GND037) U14.F18(GND038) U14.F24(GND039) U14.G1(GND040) U14.G2(GND041) U14.G9(GND042) U14.G10(GND043) U14.G11(GND044) U14.G21(GND045) U14.G26(GND046) U14.H3(GND047) U14.H4(GND048) U14.H5(GND049) U14.H14(GND050) U14.H15(GND051) U14.H16(GND052) U14.H17(GND053) U14.H18(GND054) U14.H21(GND055) U14.H24(GND056) U14.J6(GND057) U14.J7(GND058) U14.J8(GND059) U14.J9(GND060) U14.J10(GND061) U14.J11(GND062) U14.J12(GND063) U14.J21(GND064) U14.J23(GND065) U14.J26(GND066) U14.K2(GND067) U14.K4(GND068) U14.K6(GND069) U14.K13(GND070) U14.K15(GND071) U14.K17(GND072) U14.K19(GND073) U14.K21(GND074) U14.L6(GND075) U14.L10(GND076) U14.L12(GND077) U14.L14(GND078) U14.L16(GND079) U14.L18(GND080) U14.L20(GND081) U14.L23(GND082) U14.L26(GND083) U14.M6(GND084) U14.M9(GND085) U14.M11(GND086) U14.M13(GND087) U14.M15(GND088) U14.M17(GND089) U14.M19(GND090) U14.M21(GND091) U14.M23(GND092) U14.N2(GND093) U14.N4(GND094) U14.N6(GND095) U14.N8(GND096) U14.N10(GND097) U14.N12(GND098) U14.N14(GND099) U14.N16(GND100) U14.N18(GND101) U14.N20(GND102) U14.N23(GND103) U14.N26(GND104) U14.P6(GND105) U14.P9(GND106) U14.P11(GND107) U14.P13(GND108) U14.P15(GND109) U14.P17(GND110) U14.P19(GND111) U14.P23(GND112) U14.R5(GND113) U14.R8(GND114) U14.R10(GND115) U14.R12(GND116) U14.R14(GND117) U14.R16(GND118) U14.R18(GND119) U14.R20(GND120) U14.R23(GND121) U14.R26(GND122) U14.T2(GND123) U14.T4(GND124) U14.T5(NC) U14.T6(GND125) U14.T9(GND126) U14.T11(GND127) U14.T13(GND128) U14.T15(GND129) U14.T17(GND130) U14.T19(GND131) U14.T21(GND132) U14.T23(GND133) U14.T26(GND134) U14.U4(NC) U14.U6(GND135) U14.U8(GND136) U14.U10(GND137) U14.U12(GND138) U14.U14(GND139) U14.U16(GND140) U14.U18(GND141) U14.U20(GND142) U14.U23(GND143) U14.V2(GND144) U14.V4(GND145) U14.V6(GND146) U14.V9(GND147) U14.V11(GND148) U14.V13(GND149) U14.V15(GND150) U14.V17(GND151) U14.V19(GND152) U14.V21(GND153) U14.V23(GND154) U14.V26(GND155) U14.W12(GND156) U14.W18(GND157) U14.W20(GND158) U14.W22(GND159) U14.Y2(GND160) U14.Y5(GND161) U14.Y6(SD_GND01) U14.Y7(SD_GND02) U14.Y8(SD_GND03) U14.Y9(SD_GND04) U14.Y10(SD_GND05) U14.Y13(GND162) U14.Y14(GND163) U14.Y15(SD_GND06) U14.Y16(SD_GND07) U14.Y21(GND164) U14.Y23(GND165) U14.Y26(GND166) U557.E1(PGND1) U557.E2(PGND2) U557.E5(PGND3) U557.E6(PGND4) U557.F1(PGND5) U557.F2(PGND6) U557.F5(PGND7) U557.F6(PGND8) U557.G1(PGND9) U557.G2(PGND10) U557.G5(PGND11) U557.G6(PGND12) U558.1(A1) U558.2(A0) U558.7(GND) U560.3(GND1) U560.16(GND2) U560.25(GND3) U560.26(GND4) U560.27(GND5) U560.28(GND6) U561.12(SW4FB) U561.16(VSELECT) U561.19(WDI) U561.43(LDO2EN) U561.45(DGND) U561.48(SYNCIN) U561.51(AGND) U561.57(EP_GND) ; also on sheet 9 10 11 12 13 14 15 16 17 18 19 20
GND_EARTH: BH5.1 BH6.1 BH7.1 BH8.1 ; also on sheet 15 17 19 20
V1V0_GND: C36.2 C126.2 C127.2 C128.2 C1472.2 R15.2 R56.1 R887.1 U557.B5(SGND)
V1V0_MS: R15.1 U557.B3(MODE/SYNC)
V1V0_RT: R56.2 U557.A3(RT)
V1V0_SVIN: C36.1 R13.2 U557.C1(SVIN)
V1V0_TRK: C1472.1 U557.B4(TRACK_SS)
V3V3_BIAS: C1342.2 R904.2 U560.1(BIAS)
V3V3_COMP: C1471.1 R905.1 U560.22(VC)
V3V3_SW: L516.1 U560.8(SW1) U560.9(SW2) U560.10(SW3) U560.11(SW4) U560.12(SW5)
V5V0_FB: C19.1 R7.1 R886.1 U1.13(FB)
V5V0_INTVCC: C1333.2 U1.2(INTVCC)
V5V0_RT: R11.2 U1.1(RT)
V5V0_SS: C18.2 U1.15(TR/SS)
V5V0_SW: L515.1 U1.5(SW1) U1.6(SW2)
VDD_FB: C122.2 J8.1 R55.2 R59.1 U557.A5(FB)
VDD_FDIVH: C122.1 R52.2 R55.1 R894.1
VDD_FDIVL: R59.2 R60.2 R62.2 R64.1 R896.1
VDD_INTVCC: C125.1 U557.B6(INTVCC)
VDD_ITH: C127.1 R67.1 U557.A4(ITH)
VDD_LP: C163.1 J9.1 U14.G12(TA_BB_VDD) ; also on sheet 16 17
VDD_SEL: J8.2 R60.1
VDD_SW: L9.1 U557.C3(SW1) U557.C4(SW2) U557.D3(SW3) U557.D4(SW4) U557.E3(SW5) U557.E4(SW6) U557.F3(SW7) U557.F4(SW8) U557.G3(SW9) U557.G4(SW10)
VDD_VBUS: R899.1 U558.8(VBUS)
VDD_VOUTM: C126.1 R62.1 U557.A6(VOUTM)
CPU_ID: U14.R4(NC) ; also on sheet 18
CPU_USB_HVDD: C156.1 C157.1 C159.1 FL5.3(OUT_IN) U14.K8(USB_HVDD1) U14.L8(USB_HVDD2)
CPU_USB_SDVDD: C152.1 C153.1 C155.1 FL4.3(OUT_IN) U14.M7(USB_SDVDD1) U14.M8(USB_SDVDD2)
CPU_USB_SVDD: C148.1 C149.1 C151.1 FL3.3(OUT_IN) U14.K7(USB_SVDD1) U14.L7(USB_SVDD2)
CPU_VDD: C162.1 C164.1 C165.1 C166.1 C167.1 C168.1 C169.1 C170.1 C171.1 C172.1 C173.1 C174.1 C175.1 C176.1 C180.1 C181.1 C182.1 C183.1 C184.1 C185.1 C186.1 C187.1 C188.1 C189.1 C190.1 C191.1 C193.1 C194.1 C195.1 C196.1 C197.1 C198.1 C199.1 C200.1 C201.1 C202.1 C203.1 C204.1 C205.1 C206.1 C207.1 C208.1 C209.1 C210.1 C211.1 C212.1 C213.1 C214.1 C215.1 C216.1 C217.1 C218.1 C219.1 C220.1 C221.1 C222.1 C223.1 C224.1 C225.1 C226.1 C227.1 C228.1 C229.1 FL3.1(IN_OUT) FL4.1(IN_OUT) J9.2 R890.4(I2) U14.K14(VDD01) U14.K16(VDD02) U14.K18(VDD03) U14.K20(VDD04) U14.L11(VDD05) U14.L13(VDD06) U14.L15(VDD07) U14.L17(VDD08) U14.L19(VDD09) U14.M10(VDD10) U14.M12(VDD11) U14.M14(VDD12) U14.M16(VDD13) U14.M18(VDD14) U14.N9(VDD15) U14.N11(VDD16) U14.N13(VDD17) U14.N15(VDD18) U14.N17(VDD19) U14.N19(VDD20) U14.P10(VDD21) U14.P12(VDD22) U14.P14(VDD23) U14.P16(VDD24) U14.P18(VDD25) U14.R9(VDD26) U14.R11(VDD27) U14.R13(VDD28) U14.R15(VDD29) U14.R17(VDD30) U14.R19(VDD31) U14.T10(VDD32) U14.T12(VDD33) U14.T14(VDD34) U14.T16(VDD35) U14.T18(VDD36) U14.U9(VDD37) U14.U11(VDD38) U14.U13(VDD39) U14.U15(VDD40) U14.U17(VDD41) U14.U19(VDD42) U14.V10(VDD43) U14.V12(VDD44) U14.V14(VDD45) U14.V16(VDD46) U14.V18(VDD47) U14.V20(VDD48) U14.W11(VDD49) U14.W17(VDD50) U14.W19(VDD51) ; also on sheet 9
CPU_VDD_I: C113.1 C114.1 C115.1 C116.1 C118.1 C119.1 C120.1 L9.2 R52.1 R890.1(I1)
DDR_VTT: C1533.1 C1534.1 C1535.1 L536.1 U561.30(SW6FB) ; also on sheet 11
FA_VL: U14.U5(NC) ; also on sheet 9
GVDD: C1530.1 C1531.1 C1532.1 L535.1 U561.31(SW5FB) ; also on sheet 9 10 11 18
I2C1_CH0_SCL: U558.5(SCL) U561.55(SCL) ; also on sheet 16
I2C1_CH0_SDA: U558.4(SDA) U561.56(SDA) ; also on sheet 16
INA_VDD_S_N: C1335.2 R889.2 U558.9(VIN-)
INA_VDD_S_P: C1335.1 R888.1 U558.10(VIN+)
INTVCC: U560.2(INTVCC)
LS1043A_GND_SENSE: R897.2 U14.W5(NC)
LS1043A_VDD_SENSE: R893.2 U14.V5(NC)
LS1046A_GND_SENSE: R898.2 U14.G20(SENSEGND)
LS1046A_VDD_SENSE: R895.2 U14.G19(SENSEVDD)
OVDD: C1520.1 C1521.1 C1523.1 L532.1 U561.2(SW2FB) ; also on sheet 9 12 13 15 16 17 18 19
PMIC_EN: R927.2 U561.22(PWRON)
PMIC_FSOB: R936.2 U561.29(FSOB)
PMIC_INT_B: R929.2 U561.24(~{INT}) ; also on sheet 17
PMIC_LICELL: C1546.1 U561.46(LICELL)
PMIC_POR_B: R928.2 R939.1 U561.42(PGOOD)
PMIC_RESET_MCU_B: R934.2 R938.1 U561.21(~{RESET}_MCU)
PMIC_STBY: R930.1 U561.23(STANDBY)
PMIC_V1P5A: C1540.1 R937.1 U561.41(V1P5A)
PMIC_V1P5D: C1545.1 U561.40(V1P5D)
PMIC_VDDOTP: R933.1 U561.53(VDDOTP)
PS_3V3_PG: R6.1 R901.2 U560.23(PG)
PS_5V0_EN: R5.2 R6.2 U1.11(EN/UV)
PS_V5V0_PG: R10.2 U1.12(PGOOD) ; also on sheet 18
PS_VDD_EN: C1551.1 U557.B2(RUN) U561.28(LDO4OUT)
PS_VDD_PG: R66.2 U557.A2(PGOOD) ; also on sheet 18
RESET_MCU_B: R938.2 R939.2 ; also on sheet 18
SENSE_VDD: R893.1 R894.2 R895.1 R899.2
SENSE_VSS: R896.2 R897.1 R898.1
SW1LX: L531.2 U561.5(SW1LX)
SW2LX: L532.2 U561.6(SW2LX)
SW3LX: L533.2 U561.9(SW3LX)
SW5LX: L535.2 U561.33(SW5LX)
SW6LX: L536.2 U561.34(SW6LX)
SW7LX: L537.2 U561.36(SW7LX)
TA_BB_RTC: U14.F12(NC) ; also on sheet 16
VSNVS: C1550.1 U561.47(VSNVS)
N27121803: C128.1 R67.2
N27124315: R888.2 R890.2(E1) TP116.1(Pin1)
N27124319: R889.1 R890.3(E2) TP117.1(Pin1)
N27157188: C1341.2 R900.2 R902.1 U560.24(FB)
N27157490: R903.1 U560.18(RT)
N27163263: C1344.1 U560.21(SS)
N27955896: R931.1 U561.39(XINTB)
N27955915: R932.1 U561.52(AMUX)
N27960172: R935.2 U561.20(EWARN)
N27963255: C1552.1 U561.15(LDO1OUT)
N27963260: C1553.1 U561.18(LDO2OUT)
N27963345: C1554.1 U561.25(LDO3OUT)
N27963673: R937.2 U561.44(XFAILB)
N28073320: R943.1 U561.14(TBBEN)
N28345649: R964.1 U14.P21(NC)
N29940981: C1343.1 R905.2

Not connected (* = marked no-connect by the designer): U1 16(SYNC)*; U14 AA10(NC)* AA15(NC)* AB10(NC)* AB11(NC)* AB16(NC)* K9(NC)* K10(NC)* K11(NC)* K12(NC)* K22(NC)* L9(NC)* L21(NC)* M20(NC)* N21(NC)* P5(NC)* P8(NC)* P20(NC)* T8(NC)* T20(NC)* U21(NC)* V8(NC)* W7(NC)* W8(NC)* W9(NC)* W21(NC)*; U557 A1(PHMODE)* B1(CLKOUT); U558 3(NC)*; U560 7(BST) 19(CLKOUT) 20(SYNC/MODE); U561 1(NC1) 10(SW4LX)* 49(SYNCOUT)*

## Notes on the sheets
sheet 1
- Rev
- Date
- Changes
- Table of Contents
- A
- 18-JAN-2019
- FRWYLS1046A-PA  (PROTOTYPE)
- 1
- TITLE
- B
- 18-MAR-2019
- 1) Changed R142 to 100ohm.
  2) Changed logic for PROG_SFP circuit.
  3) Replaced J66 with Header 210-75691.
  4) Replaced J67 with Header 211-30042.
  5) Added Bypass caps between DDR_VTT and GVDD power rails.
  7) Replaced Micro-AB J58 with Molex 0476420001 Micro-B part.
  8) Added Header for 12V CPU fan "J75".
  9) DNP-> R920 and C1466.
  10) Change BRD_REV[1:0]=01 for Rev B.
- 2
- BLOCK DIAGRAM
- 3
- PCB STACKUP
- 4
- POWER_ARCH
- 5
- PS_12VIN,5V,3V3
- 6
- PS_DDR_VR5100_PMIC
- 7
- PS_VDD
- 8
- CPU_POWER1
- 9
- CPU_POWER2
- 10
- CPU DDR4 CTRL & SDRAM PART1
- 11
- DDR4 SDRAM PART2
- 12
- CPU_QSPI & NAND
- 13
- CPU SERDES & CLOCKS
- 14
- M.2_PCIe_CARD
- 15
- QSGMII PHY (F104)
- 16
- I2C_INTERFACE
- 17
- CPU USB[1:3]
- 18
- CPU MISC. &UART
- 19
- CPU_RESET and GPIOs
- 20
- SD_SPI_MIKRO_CLICK
- FRWYLS1046A-PA
sheet 5
- MOUNTING HOLES
- AC ADAPTER SPECIFICATIONS
- DC Voltage Output: 12VDC
- Current Output: ~ 5A (depending on application)
- Polarity:
- Plug/Mating Plug Diameter: Barrel Style 2.1mm ID, 5.5mm OD, L=11mm
- Plug/Mating Plug Diameter:
  2.1mm ID, 5.5mm OD
- Adaptor Power No: > PN:GST60A12-P1J    12V @ 5A [Meanwell]
- 5V0 POWER SUPPLY
- 5V @2A
- (>1.2V)
- *Soft Start
              Tss = C*0.774/2u
              Tss = 0.01u*0.774/2u  = 3.87msec
- Switching Freq: 2MHz
- 3V3@ 10A  POWER SUPPLY
- 3.3V @10A
sheet 6
- PF8100 PMIC POWER SUPPLY
- I2C address: 0x08
- Place one Cap near to each power input pin
- #1        #2           #3            #4             #5            #6            #7
- 1V0 @ 1A
- BUCK1 (MASTER/SLAVE)
  (0.4 V TO 1.8 V, 2.5 A)
- #1
- (1.5 V TO 5 V, 400 mA)
- BUCK2 (MASTER/SLAVE)
  (0.4 V TO 1.8 V, 2.5 A)
- #2
- 1.8V
- BUCK3 (MASTER/SLAVE)
  (0.4 V TO 1.8 V, 2.5 A)
- #3
- 1.8V@2A
- BUCK4 (MASTER/SLAVE)
  (0.4 V TO 1.8 V, 2.5 A)
- #4
- #5
- BUCK5 (MASTER/SLAVE)
  (0.4 V TO 1.8 V, 2.5 A)
- 1V35 @ 400mA
- BUCK6 (MASTER/SLAVE)
  (VTT/0.4 V TO 1.8 V, 2.5 A
- #6
- #7
- PF8100 CONFIGURATION
  ** SW1 -> 1V  [QSGMII PHY]
  ** SW2 -> 1.8V [LS1046]
  ** SW3 -> 1.35V [LS1046]
  ** SW4 -> Unused
  ** SW5-> 1.2V [LS1046, DDR4]
  ** SW6 -> 0.6V
  ** SW7 -> 2.5V [QSGMII PHY and LS1046]
  ** LDO1, LDO2, LDO3 -> 1.8V [DON'T CARE]
  ** LDO4 -> 1.8V (VDD ENABLE)
  SEQUENCE:
  -> 2.5V,1.8,1.35,(Unused LDO1, LDO2, LDO3)
  -> 1.0, LDO4 (VDD ENABLE)
  -> 1.2V and 0.6V
  -> PGOOD, MCU_RESET_B
- BUCK7 (INDEPENDENT)
  (1.0 V TO 4.1 V, 2.5 A)
- 1.2V @ 3A
- 0.60V @ 1A
- 2V5 @ 1A
sheet 7
- Power/Current
  Monitor
- 7-Bit Address = 0x40
- VDD PS: 1.0V/0.9V±3% @ 20A
- Rx
- Open:VDD=0.9V
  Close:VDD=1.0V
- Rt
- Ry
- (>1.2V)
- Place near regulator
- Place near regulator
- LTC7150 CONFIGURATION
  * VOUT
  VOUT = 0.6 * [1+(Rx/Ry)]
  VOUT = 1.0/0.9V
  * RT(FREQUENCY)
  FSW = 1.67E11 / RT
  FSW = 633 kHz
  * TRACK/SS
  Soft-start: formula TBD
  * MODE/SYNC
  GND = discontinuous
  FLOAT = forced continuous
  * PHMODE
  FLOAT = 2phase (internal)
  * ITH (LOOP COMPENSATION)
  See spec.
- Analog diff pair
sheet 8
- LS1043A_FA_VL
- Note:
  Those NC pins are used for support of both LS1046A and LS1043A.
